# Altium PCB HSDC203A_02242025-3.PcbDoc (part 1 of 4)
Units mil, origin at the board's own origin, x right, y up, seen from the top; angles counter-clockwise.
Board outline 5612.98 x 3012.39 mil, 6 copper layers (Top Layer, GND1, Signal1, Power, GND2, Bottom Layer), stack 60.4 mil thick; 301 components, 211 nets, 1107 pads, 249 vias.
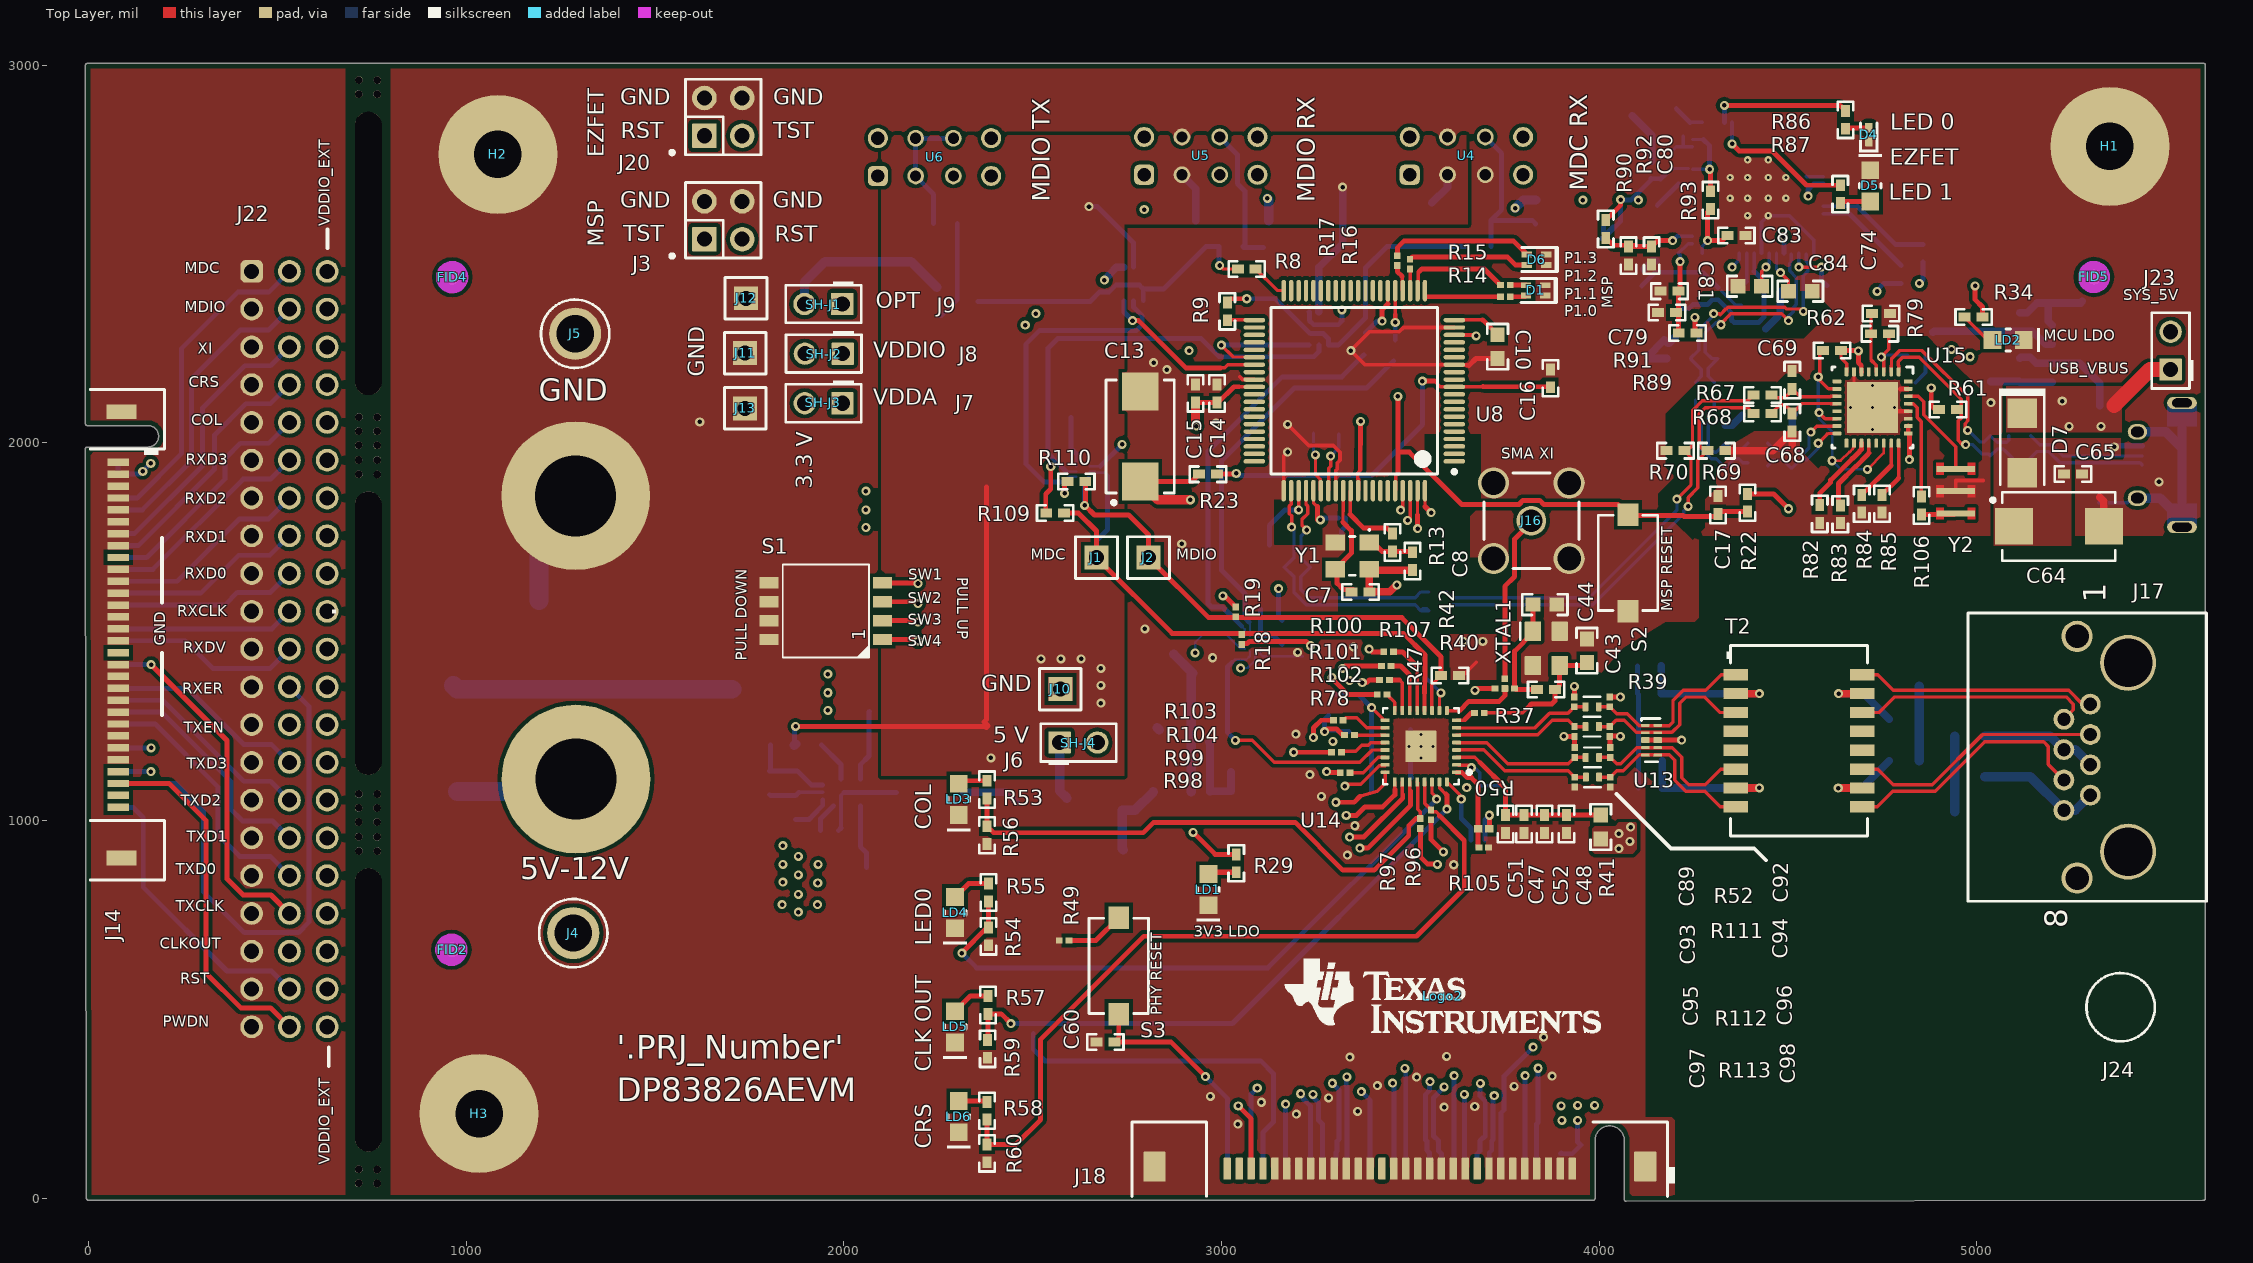
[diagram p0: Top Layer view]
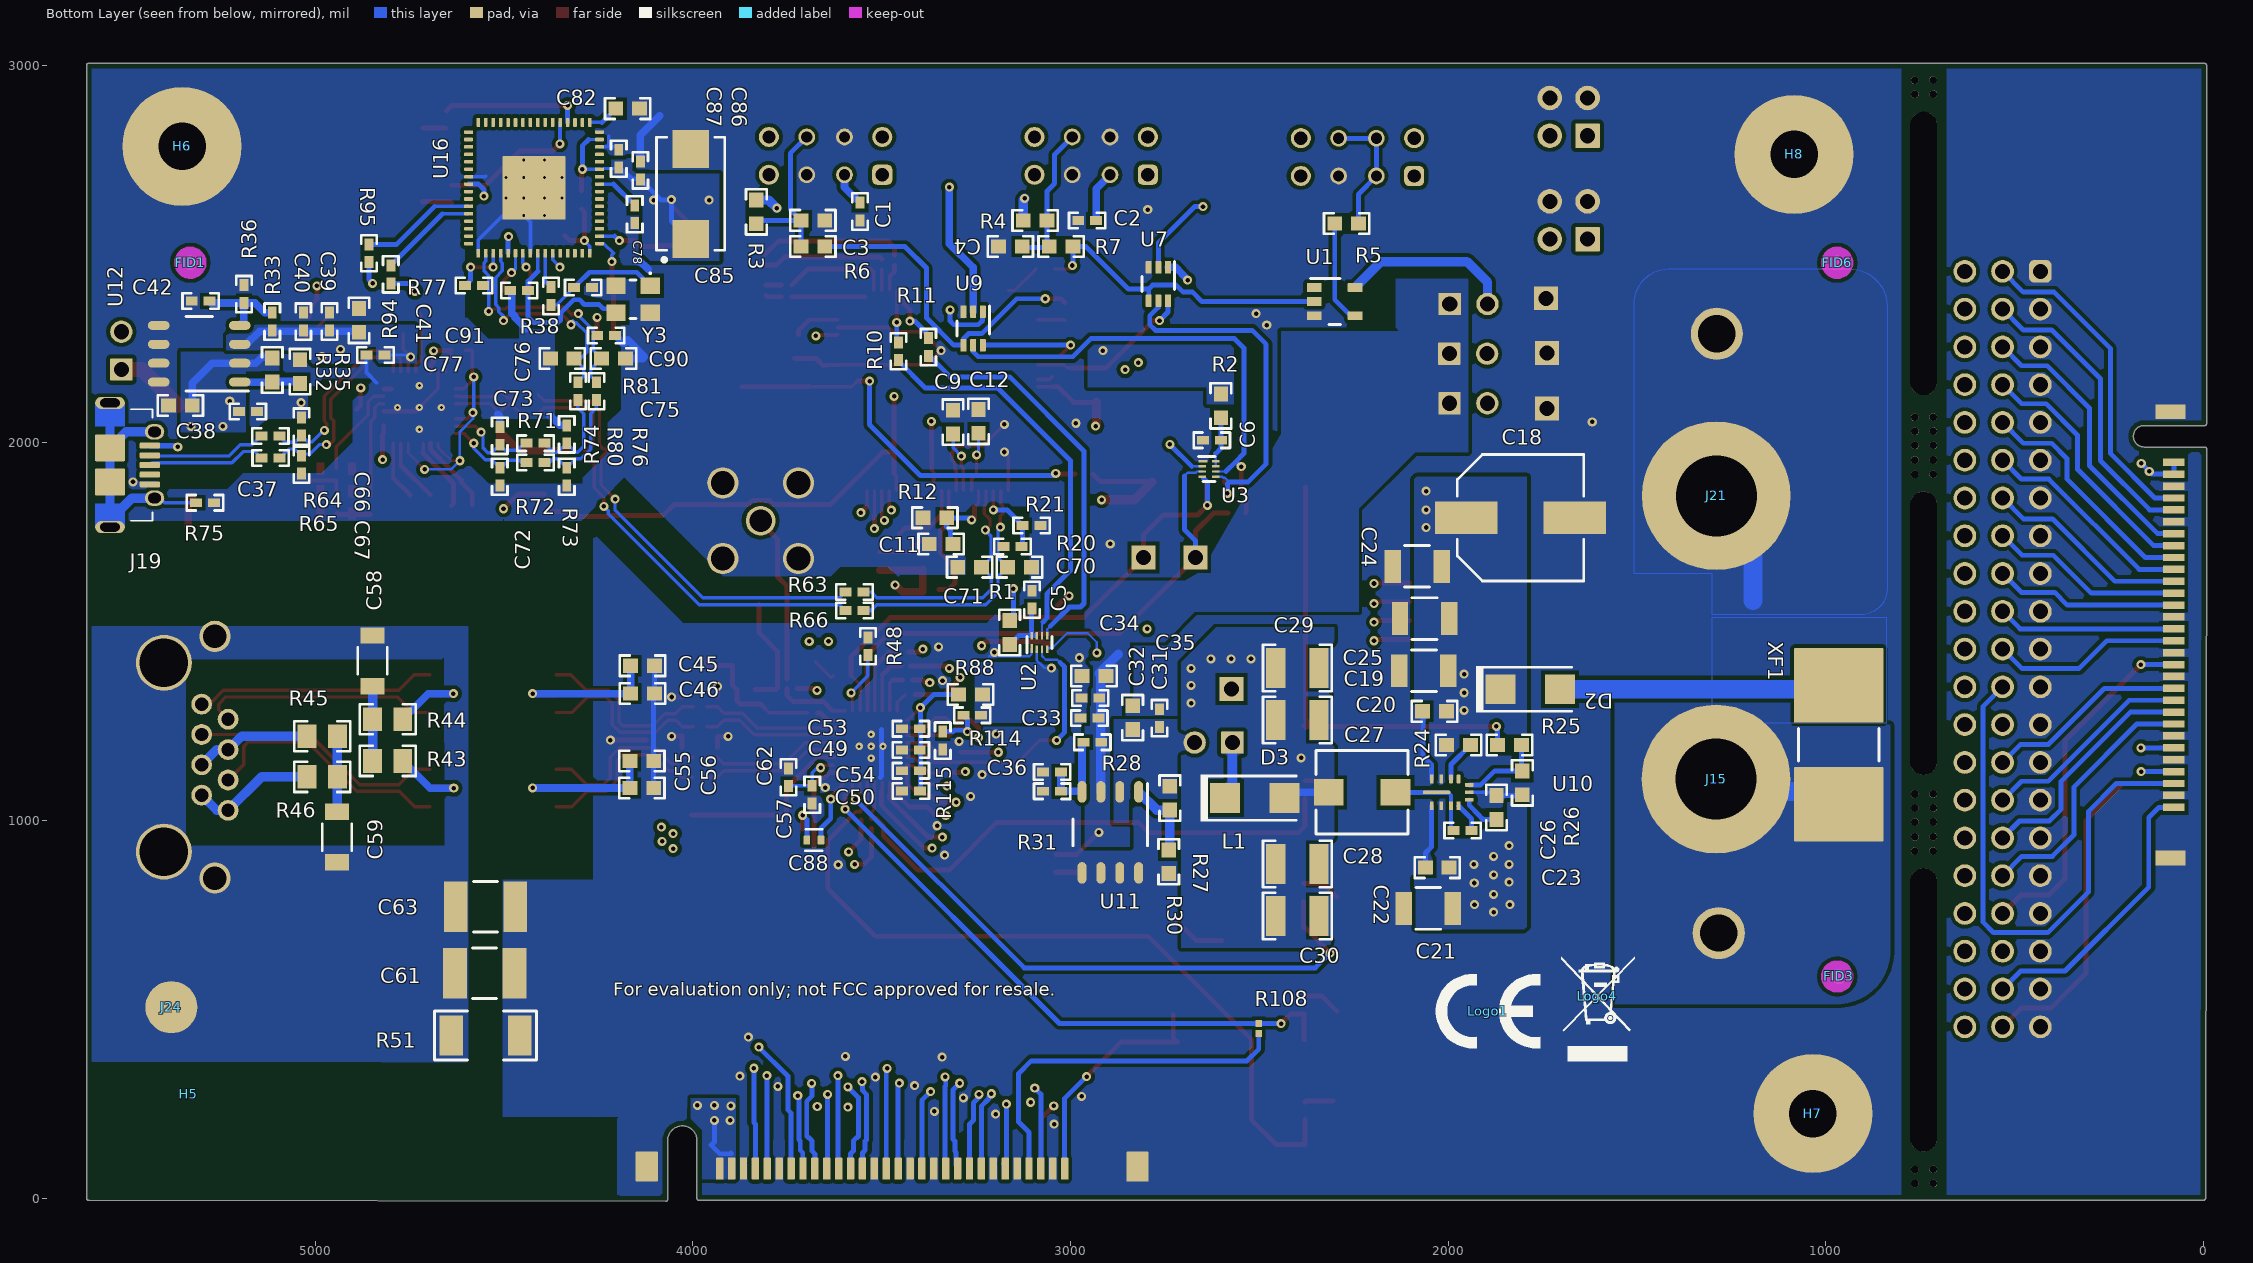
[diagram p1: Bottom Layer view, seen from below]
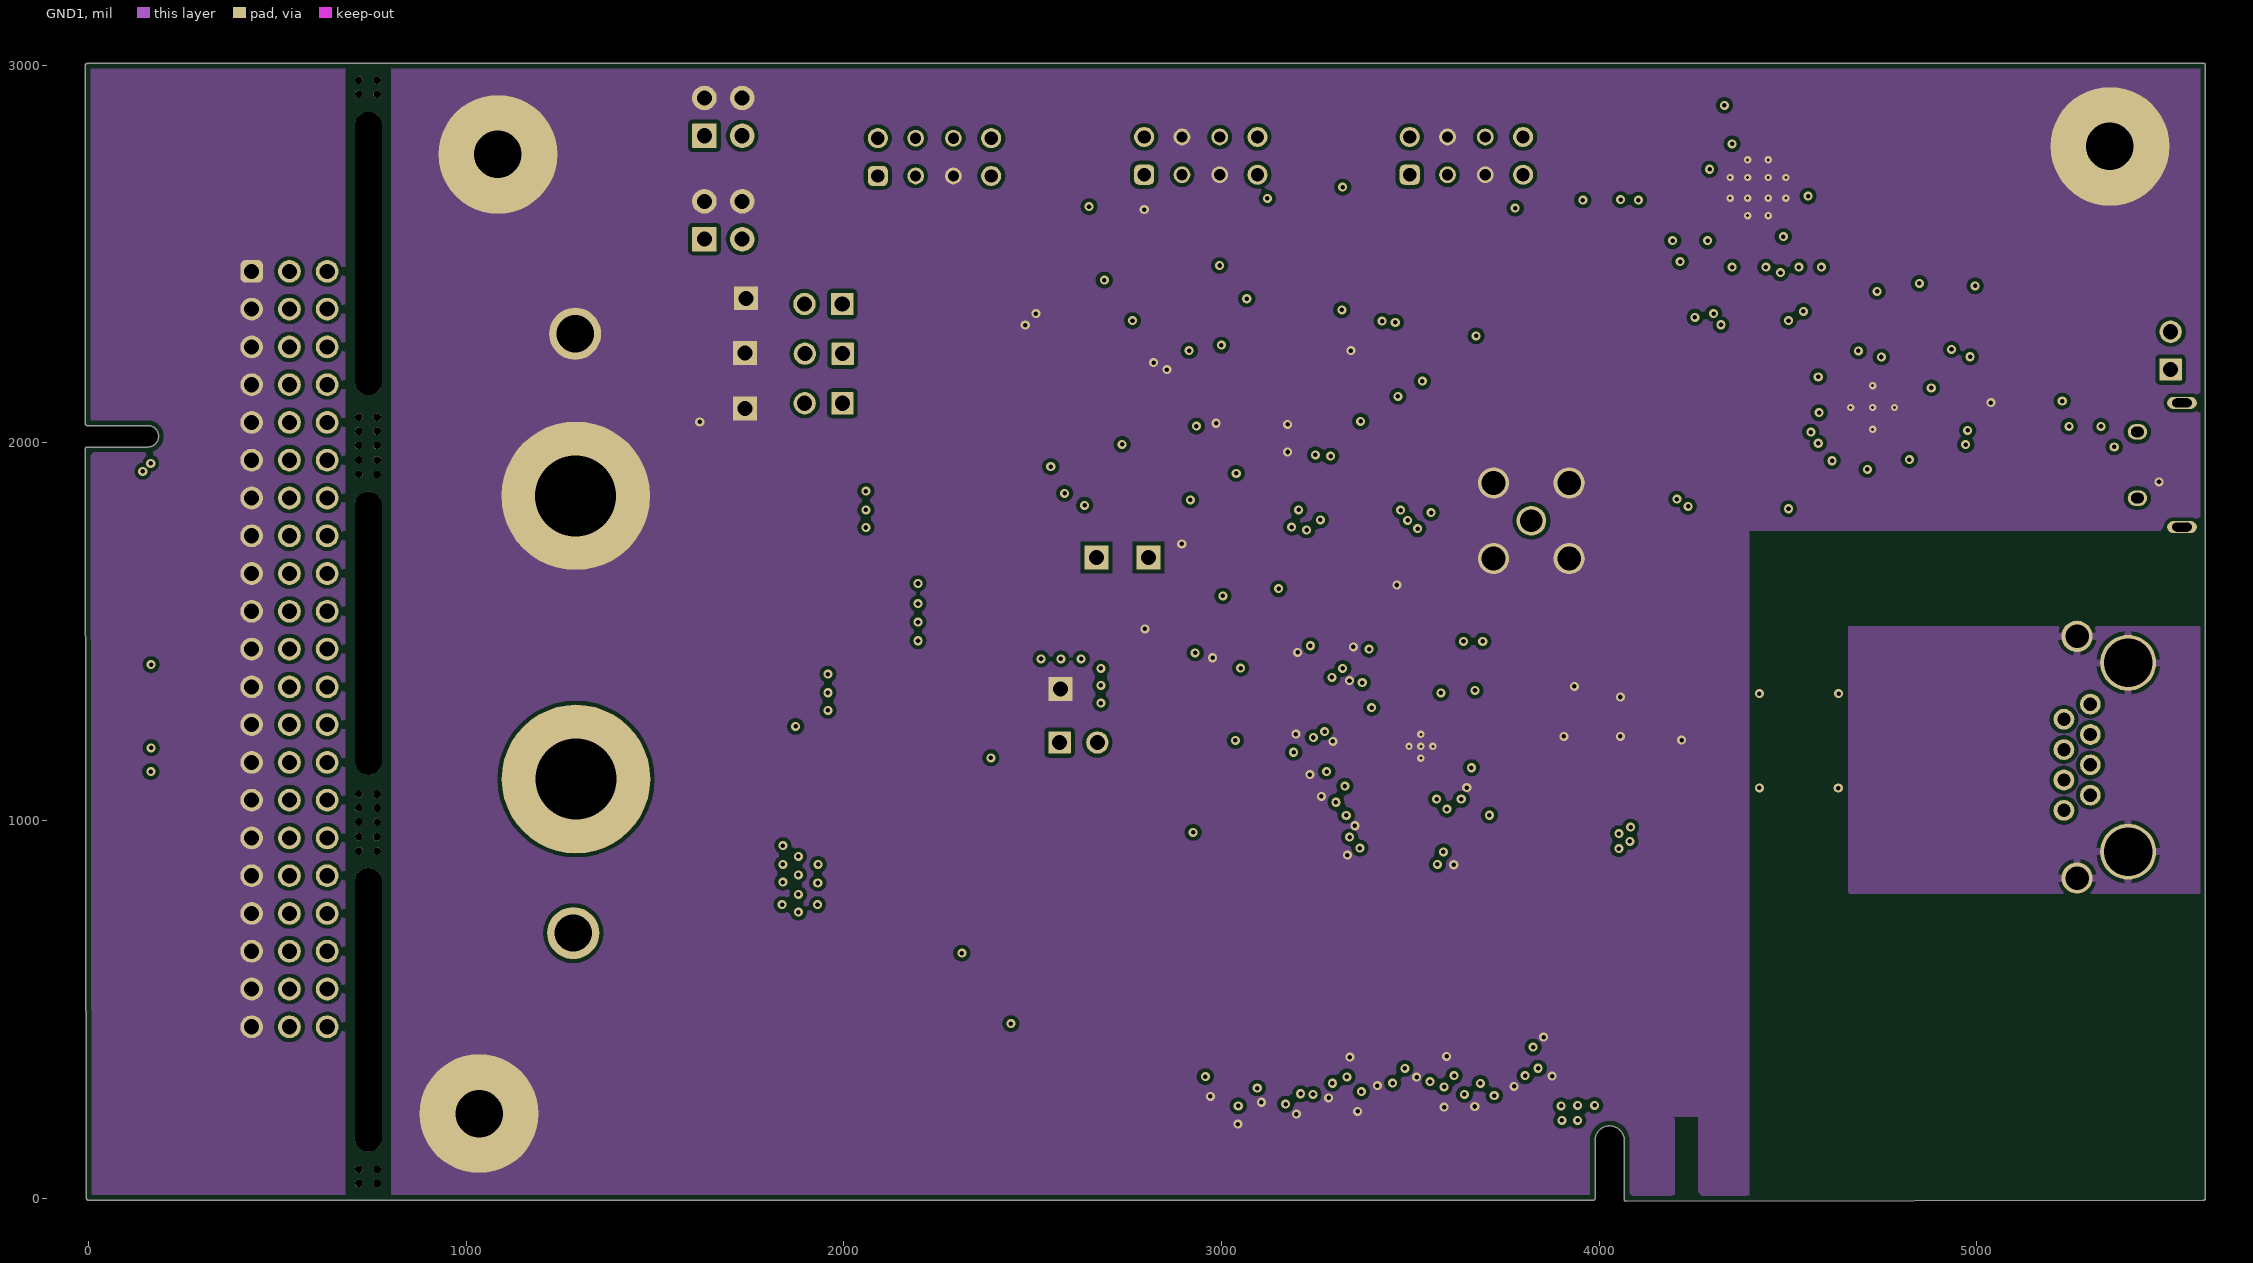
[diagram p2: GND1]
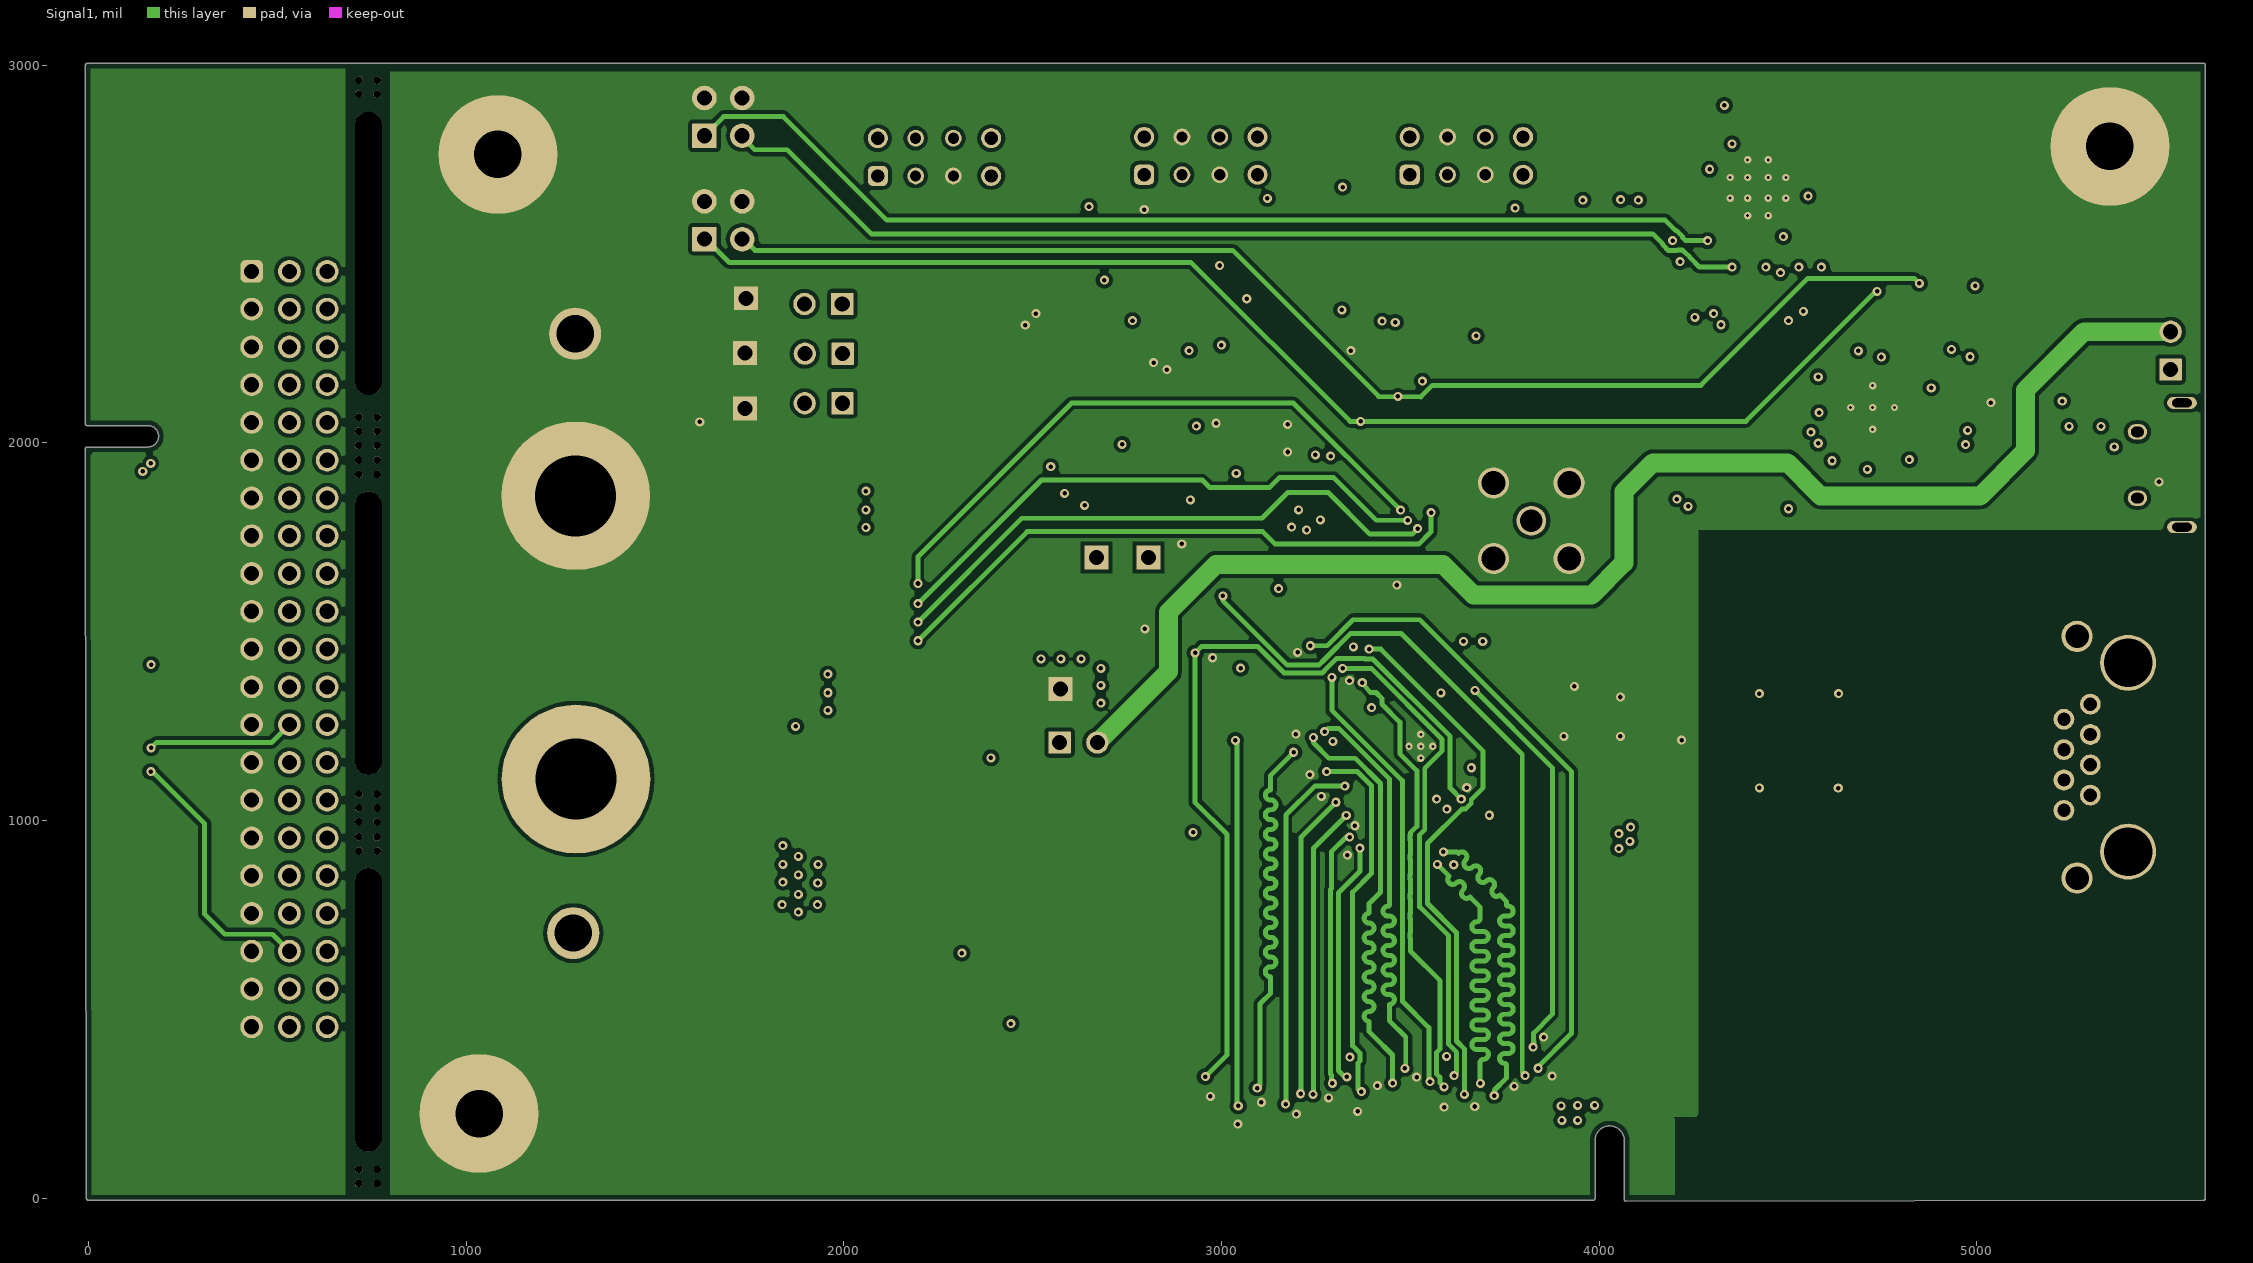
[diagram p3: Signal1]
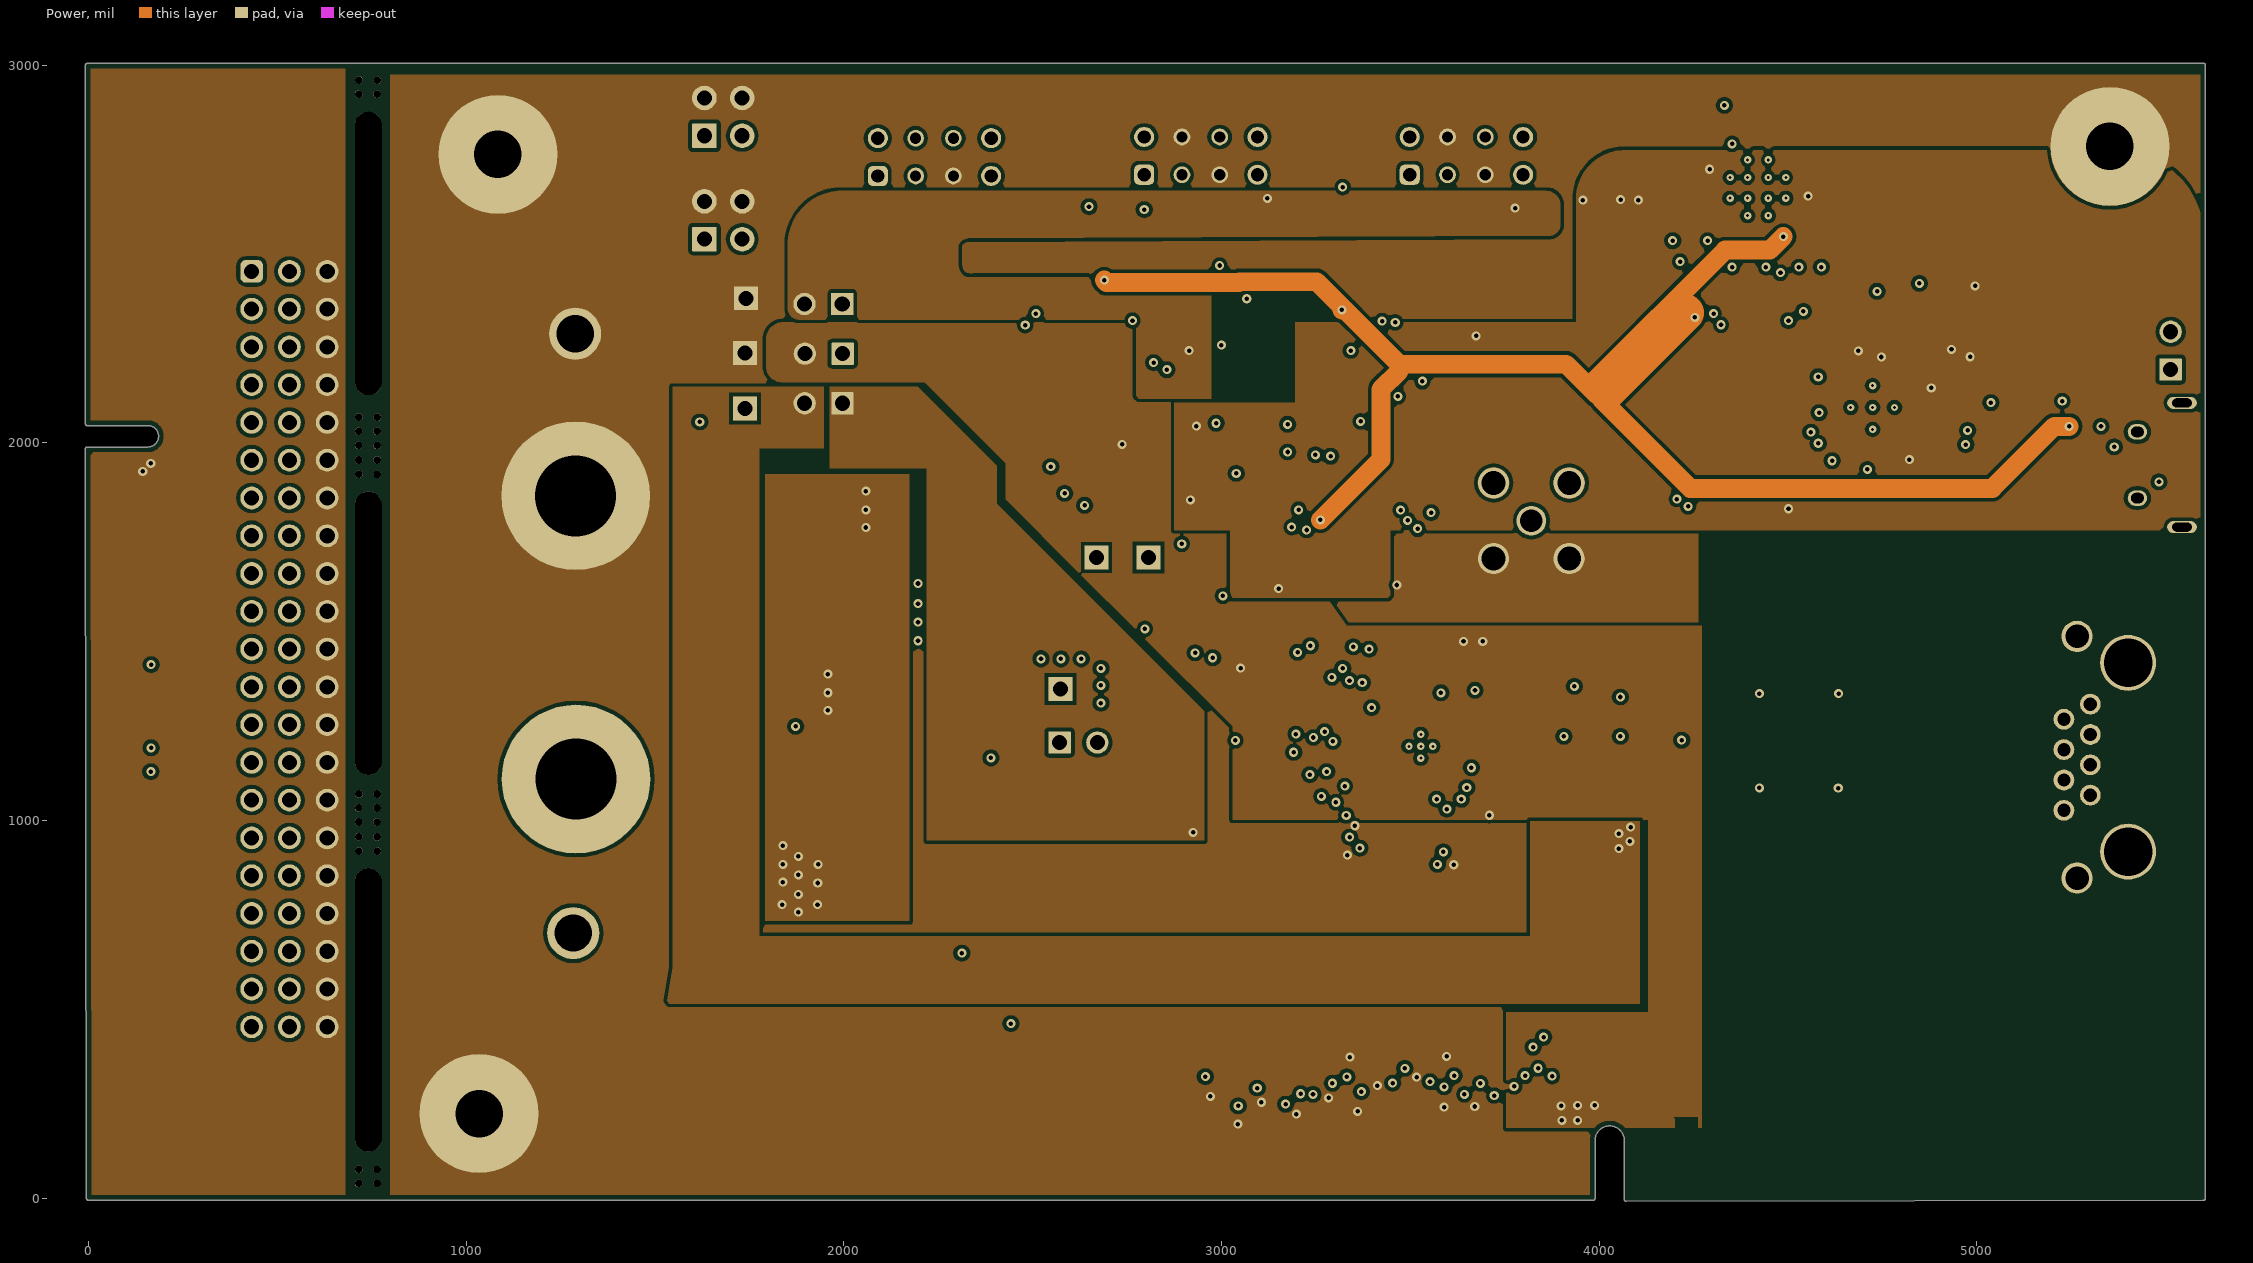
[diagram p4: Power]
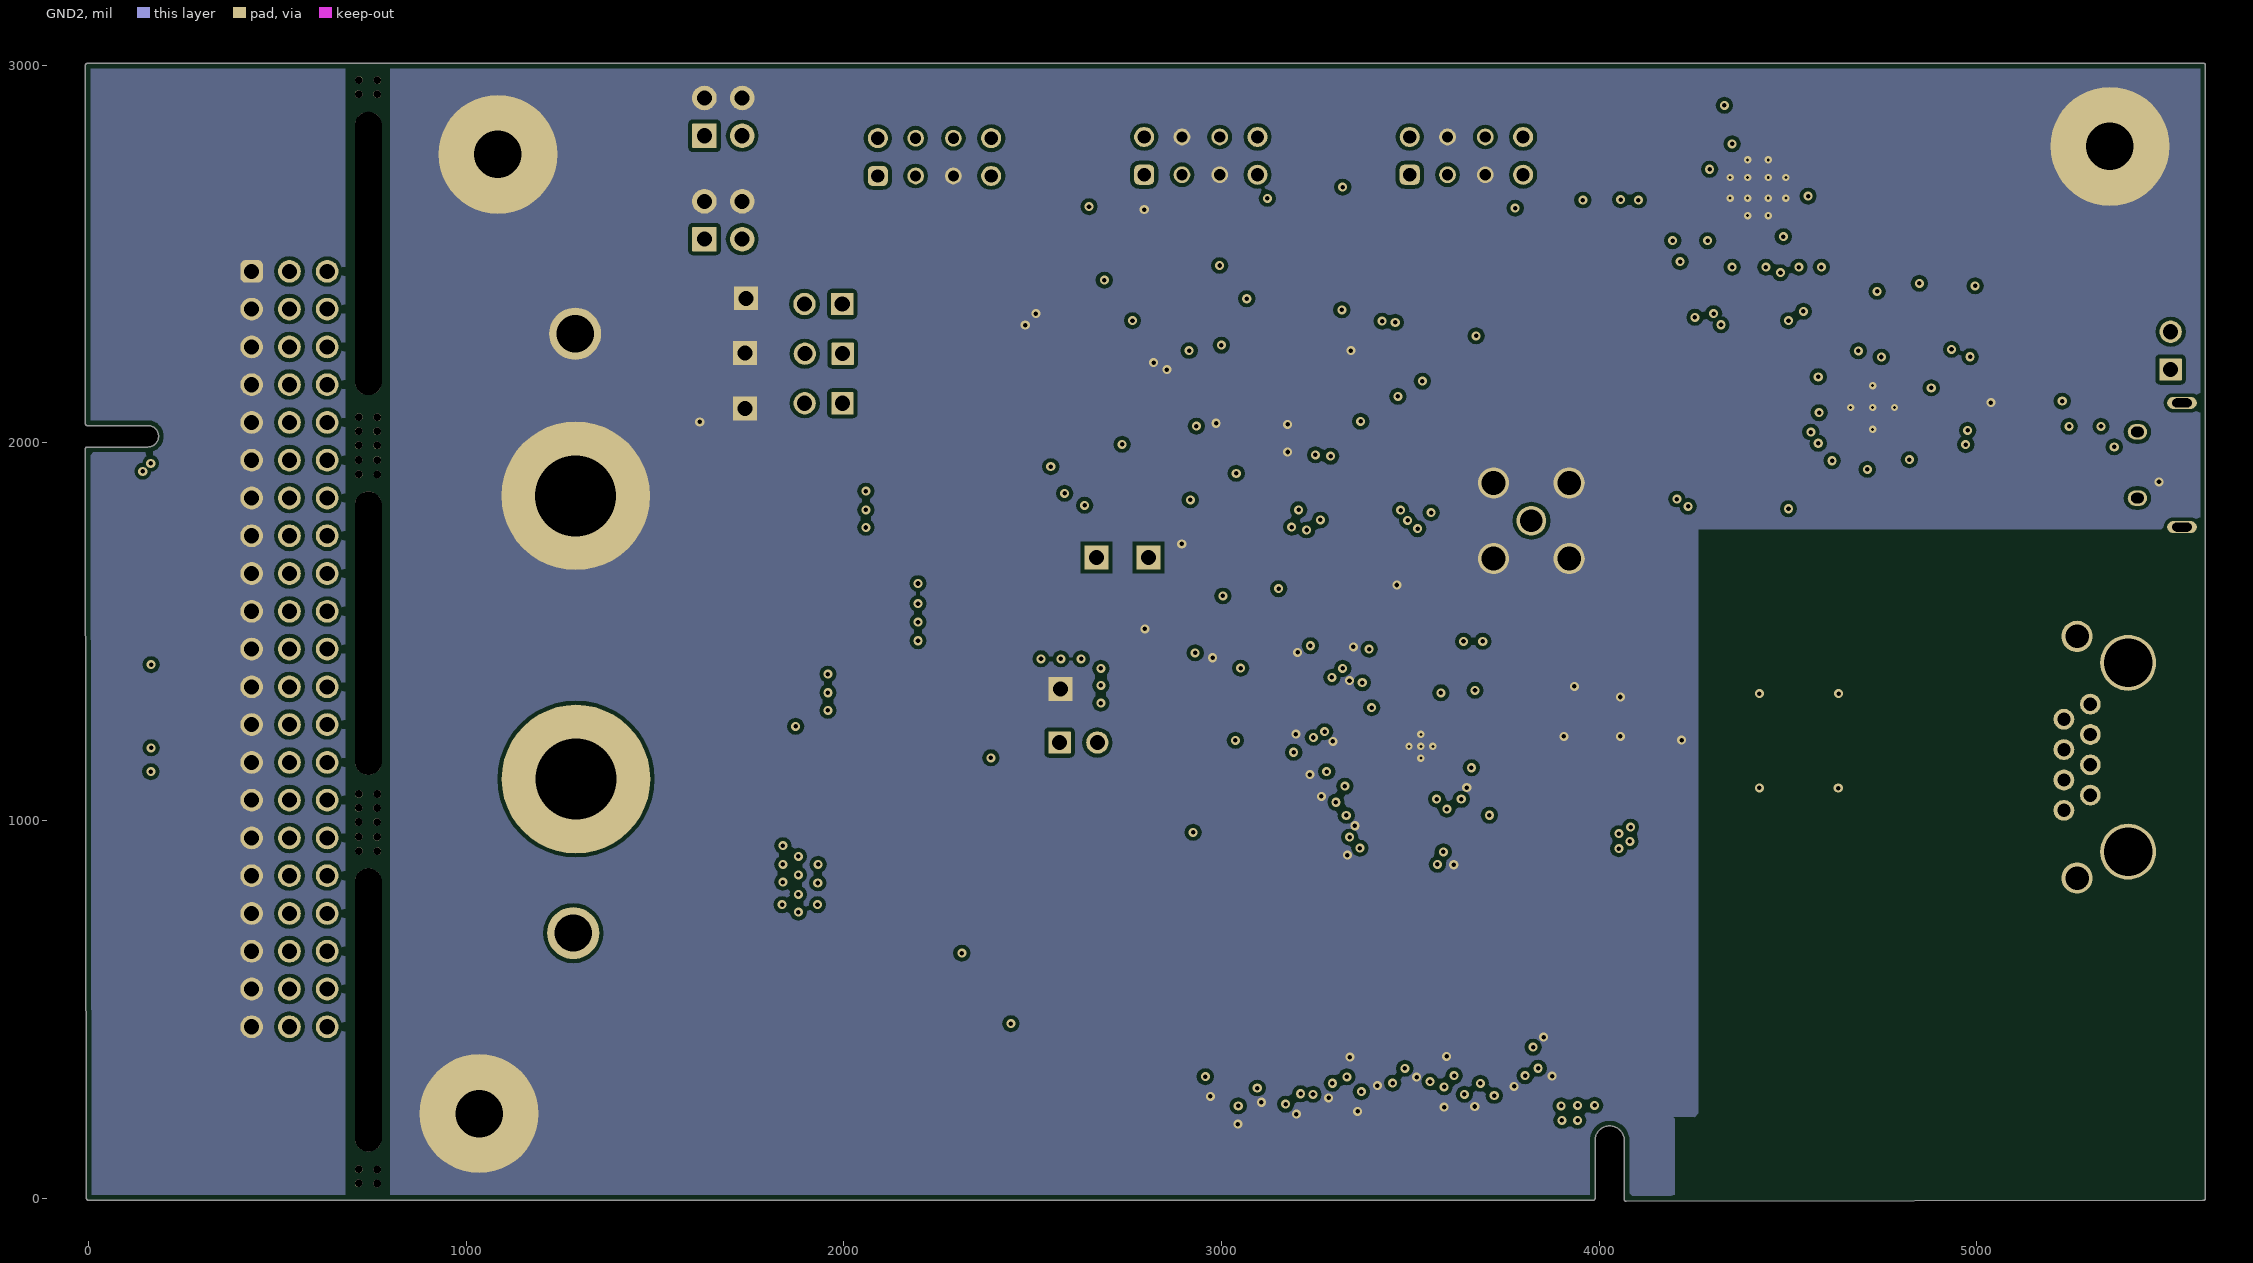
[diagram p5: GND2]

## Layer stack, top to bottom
Top Solder: solder mask 0.7, Solder Resist, Dk 3.5
Top Layer: signal copper 1.4
Dielectric 1: dielectric 7, FR-4 High TG, Dk 4.2
GND1: signal copper 1.4
Dielectric1: core 14, FR-4 High TG, Dk 4.2
Signal1: signal copper 1.4
Dielectric 2: dielectric 10, FR-4 High TG, Dk 4.2
Power: signal copper 1.4
Dielectric 4: core 14, FR-4 High TG, Dk 4.2
GND2: signal copper 1.4
Dielectric 3: dielectric 7, FR-4 High TG, Dk 4.2
Bottom Layer: signal copper 1.4
Bottom Solder: solder mask 0.4, Solder Resist, Dk 3.5

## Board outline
-5.01,-0.01 -7.97,1984.24 cw(c-2.95,1984.25) -2.95,1989.27 157.48,1989.27 ccw(c157.48,2017.72) 185.93,2017.72 ccw(c157.48,2017.72) 157.48,2046.17 -2.95,2046.17 cw(c-2.95,2051.18) -7.97,2051.18 -7.96,3000 cw(c-2.95,3000) -2.88,3005.01 5600,3005.02 cw(c5600,3000) 5605.02,3000 5605.02,0 cw(c5600,0) 5599.02,-4.92 5598.04,-5.02 4071.27,-7.38 cw(c4071.26,-2.36) 4066.39,-1.18 4066.24,0 4066.24,157.76 ccw(c4027.56,152.84) 3988.87,157.76 3988.87,0 cw(c3983.86,0) 3983.86,-5.02 0,-5.02 cw(c0,0)

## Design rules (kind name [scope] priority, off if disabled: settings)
AcuteAngle [All] p1: minimum=4.50000000000000E+0001 checktracksonly=FALSE
AssemblyTestPointUsage [All] p1: valid=2
BoardOutlineClearance BoardOutlineClearance_MountingHoles [OnCopper and InComponentClass('Mounting Holes')] p1: gap=39.37 ignorepadtopadclearanceinfootprint=FALSE
BoardOutlineClearance BoardOutlineClearance_Poly [OnCopper and IsPoly] p2: gap=14 ignorepadtopadclearanceinfootprint=FALSE
BoardOutlineClearance [OnCopper and Not InComponentClass('Logo') and not InComponentClass('FiducialMark') and not InRegion(1000,500,4000,800) and not InPoly] p3: gap=14 ignorepadtopadclearanceinfootprint=FALSE
Clearance Clearance_Keepouts [((IsTrack Or IsArc) And Not InPoly) And IsFree and IsKeepOut vs ((IsTrack Or IsArc) And Not InPoly) And IsFree and IsKeepOut] p1: gap=0 ignorepadtopadclearanceinfootprint=FALSE
Clearance Clearance_Poly [InPolygon] p2: gap=10 ignorepadtopadclearanceinfootprint=TRUE
Clearance Clearance_FiducialMark [IsKeepOut and InComponentClass('FiducialMark') vs IsPad and InComponentClass('FiducialMark')] p3: gap=0 ignorepadtopadclearanceinfootprint=FALSE
Clearance [All] p4: gap=7.87 ignorepadtopadclearanceinfootprint=TRUE except(7.3: Arc-Arc Arc-Track Arc-SMDPad Arc-Via Track-Track Track-SMDPad Track-Via)
ComponentClearance ComponentClearance_CLK_Res [InComponent('R107')  Or  InComponent('R40')  Or  InComponent('R42')] p1: gap=0 collisioncheckmode=3 verticalgap=0 showdistances=FALSE
ComponentClearance ComponentClearance_MountingHoles_FiducialMarks [InComponentClass('Mounting Holes') vs InComponentClass('FiducialMark')] p2: gap=50 collisioncheckmode=3 verticalgap=10 showdistances=FALSE
ComponentClearance ComponentClearance_Shunt [InComponentClass('Header') vs InComponentClass('Shunt')] p3: gap=0 collisioncheckmode=3 verticalgap=0 showdistances=FALSE
ComponentClearance ComponentClearance_Logo [InComponentClass('Logo')] p4: gap=50 collisioncheckmode=3 verticalgap=10 showdistances=FALSE
ComponentClearance ComponentClearance_ScrewToNut [(HasFootprint('NY PMS 440 0025 PH')) vs (HasFootprint('Keystone_1902E'))] p5: gap=5 collisioncheckmode=3 verticalgap=10 showdistances=FALSE
ComponentClearance ComponentClearance_MountingHoles [InComponentClass('Mounting Holes')] p6: gap=250 collisioncheckmode=3 verticalgap=100000 showdistances=FALSE
ComponentClearance ComponentClearance_SmallPassives [HasFootprint('0201*') or HasFootprint('0402*') or HasFootprint('0508') or HasFootprint('0603*') or HasFootprint('0612') or HasFootprint('0805*') or HasFootprint('0815*') or HasFootprint('0830*') or HasFootprint('1206*') or HasFootprint('1210*') or HasFootprint('1808*') or HasFootprint('1812*') or HasFootprint('1825*') or HasFootprint('2010*') or HasFootprint('2220*') or HasFootprint('2225*') or HasFootprint('2512*') or HasFootprint('2728*') or HasFootprint('3518*') vs HasFootprint('0201*') or HasFootprint('0402*') or HasFootprint('0508') or HasFootprint('0603*') or HasFootprint('0612') or HasFootprint('0805*') or HasFootprint('0815*') or HasFootprint('0830*') or HasFootprint('1206*') or HasFootprint('1210*') or HasFootprint('1808*') or HasFootprint('1812*') or HasFootprint('1825*') or HasFootprint('2010*') or HasFootprint('2220*') or HasFootprint('2225*') or HasFootprint('2512*') or HasFootprint('2728*') or HasFootprint('3518*')] p7: gap=14.96 collisioncheckmode=3 verticalgap=10 showdistances=FALSE
ComponentClearance ComponentClearance_THtoSMT [IsThruComponent vs IsSMTComponent] p8: gap=10 collisioncheckmode=3 verticalgap=30 showdistances=FALSE
ComponentClearance ComponentClearance_THtoTH [IsThruComponent vs IsThruComponent] p9: gap=30 collisioncheckmode=3 verticalgap=30 showdistances=FALSE
ComponentClearance [All] p10: gap=20 collisioncheckmode=3 verticalgap=10 showdistances=FALSE
DiffPairsRouting [All] p1: maxlimit=9 minlimit=9 mostfreqgap=9 toplayer_minwidth=8 toplayer_maxwidth=9 toplayer_prefwidth=9 midlayer1_minwidth=9 midlayer1_maxwidth=9 midlayer1_prefwidth=9 midlayer2_minwidth=9 midlayer2_maxwidth=9 midlayer2_prefwidth=9 midlayer3_minwidth=9 midlayer3_maxwidth=9 midlayer3_prefwidth=9 midlayer4_minwidth=9 midlayer4_maxwidth=9 midlayer4_prefwidth=9 bottomlayer_minwidth=8 bottomlayer_maxwidth=9 bottomlayer_prefwidth=9 maxuncoupledlength=1000
FabricationTestPointUsage TestPointUsage [All] p1: valid=2 allowmultiple=FALSE
FabricationTestpoint Testpoint [All] p1: side=3 testpointundercomponent=TRUE minsize=40 maxsize=100 preferedsize=60 minholesize=0 maxholesize=40 preferedholesize=32 testpointgrid=1 allowsidetop=TRUE allowsidebottom=TRUE usegrid=TRUE gridtolerance=0.01
FanoutControl Fanout_LCC [IsLCC] p1: bgadir=Out bgaviamode=Centered fanoutstyle=Auto fanoutdirection=Alternating viagrid=1 // Fanout_LCC (Default Rule)
FanoutControl Fanout_BGA [IsBGA] p2: bgadir=Out bgaviamode=Centered fanoutstyle=Auto fanoutdirection=Alternating viagrid=1 // Fanout_BGA (Default Rule)
FanoutControl Fanout_Default [All] p4: bgadir=Out bgaviamode=Centered fanoutstyle=Auto fanoutdirection=Alternating viagrid=1 // Fanout_Default (Default Rule)
FanoutControl Fanout_Small [(CompPinCount < 5)] p5: bgadir=Out bgaviamode=Centered fanoutstyle=Auto fanoutdirection=OutThenIn viagrid=1 // Fanout_Small (Default Rule)
Height [All] p1: minheight=0 maxheight=1005 prefheight=500
HoleSize HoleSize_1 [IsPad And HasSlotHole] p1: absolutevalues=TRUE maxlimit=751 minlimit=1 maxpercent=80.000 minpercent=20.000
HoleSize [All] p2: absolutevalues=TRUE maxlimit=300 minlimit=6 maxpercent=80.000 minpercent=20.000
MinimumAnnularRing MinimumAnnularRing_J19 [InComponent('J19')] p1: minimumring=3.9
MinimumAnnularRing MinimumAnnularRing_ThermalPadVias [IsVia and InAnyComponent] p2: minimumring=5.91
MinimumAnnularRing [All] p3: minimumring=5
MinimumSolderMaskSliver MinimumSolderMaskSliver_U2U3 [InPadClass('All Pads')] p1: minsoldermaskwidth=3
MinimumSolderMaskSliver MinimumSolderMaskSliver_Logo [InComponentClass('Logo') vs InComponentClass('Logo')] p2: minsoldermaskwidth=0.7
MinimumSolderMaskSliver [All] p3: minsoldermaskwidth=3.94
PlaneConnect [All] p1: planeconnectstyle=Direct reliefexpansion=10 reliefentries=4 reliefconductorwidth=10 reliefairgap=10
PolygonConnect PolygonConnect_EGND [InNet('EARTH_GND') vs OnLayer('GND1')] p1: connectstyle=Relief reliefconductorwidth=20 reliefentries=4 polygonreliefangle="90 Angle" airgapwidth=10
PolygonConnect [All] p2: connectstyle=Direct reliefconductorwidth=20 reliefentries=4 polygonreliefangle="90 Angle" airgapwidth=10
RoutingVias ThermalPadVias [IsVia and InAnyComponent] p1: holewidth=7.87 width=19.68 viastyle="Through Hole" minholewidth=7.87 minwidth=19.68 maxholewidth=12.99 maxwidth=23.62
RoutingVias [All] p2: holewidth=12 width=24 viastyle="Through Hole" minholewidth=6 minwidth=12 maxholewidth=40 maxwidth=65
ShortCircuit ShortCircuit_Y2 [InComponent('Y2')] p1: allowed=TRUE
ShortCircuit [All] p2: allowed=FALSE
SilkToBoardRegionClearance [Not ((IsComment or IsDesignator) And (Hide <> 'False')) and not InRegion(1000,500,4000,800)] p1:
SilkToSilkClearance SilkToSilkClearance_Pb-FreeLogo [(HasFootprint('Pb-Free_Overlay_Medium') OR HasFootprint('Pb-Free_Overlay_Small')) vs (HasFootprint('Pb-Free_Overlay_Medium') OR HasFootprint('Pb-Free_Overlay_Small'))] p1: silktosilkclearance=0
SilkToSilkClearance [All] p2: silktosilkclearance=3.94
SilkToSolderMaskClearance [InComponent('D2')  OR InComponent('D3')] p1: minsilkscreentomaskgap=3.9 clearancetoexposedcopper=TRUE
SilkToSolderMaskClearance SilkToComponentPadClearance [(IsPad or IsFill or IsRegion) and InAnycomponent] p2: minsilkscreentomaskgap=4 clearancetoexposedcopper=TRUE
SilkToSolderMaskClearance "Silk to Solder Mask Opening" [All] p3: minsilkscreentomaskgap=3.94 clearancetoexposedcopper=FALSE
SolderMaskExpansion [All] p1: expansion=1.97 istentingtop=FALSE
SupplyNets "Schematic Supply Nets_12" [InNet('3V3_LDO')] p1: voltage=0.000
SupplyNets "Schematic Supply Nets_11" [InNet('GND_EXT')] p2: voltage=0.000
SupplyNets "Schematic Supply Nets_10" [InNet('VDDIO')] p3: voltage=0.000
SupplyNets "Schematic Supply Nets_9" [InNet('5V-12V')] p4: voltage=0.000
SupplyNets "Schematic Supply Nets_8" [InNet('VDDIO_EXT')] p5: voltage=0.000
SupplyNets "Schematic Supply Nets_7" [InNet('USB_VBUS')] p6: voltage=0.000
SupplyNets "Schematic Supply Nets_6" [InNet('EARTH_GND')] p7: voltage=0.000
SupplyNets "Schematic Supply Nets_5" [InNet('5V')] p8: voltage=0.000
SupplyNets "Schematic Supply Nets_4" [InNet('VDDA3P3')] p9: voltage=0.000
SupplyNets "Schematic Supply Nets_2" [InNet('GND')] p10: voltage=0.000
SupplyNets "Schematic Supply Nets_1" [InNet('3V3_OPT')] p11: voltage=0.000
SupplyNets "Schematic Supply Nets" [InNet('MCU_VCC')] p12: voltage=0.000
Width [All] p1: maxlimit=100 minlimit=6 preferedwidth=13 midlayer1_minwidth=7 midlayer2_minwidth=7 midlayer3_minwidth=7 midlayer4_minwidth=7 minimp=50.000000 maximp=50.000000 favimp=50.000000 checkconnectedcopper=TRUE
13 further rules are at their usual default settings.

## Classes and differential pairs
component class SHUNT: SH-J1 SH-J2 SH-J3 SH-J4
component class HSDC203A_Power: C18 C19 C20 C21 C22 C23 C24 C25 C26 C27 C28 C29 C30 C31 C32 C33 C34 C35 C36 C37 C38 C39 C40 C41 C42 D2 D3 J4 J5 J6 J7 J8 J9 J10 J11 J12 J13 J15 J21 J23 L1 LD1 LD2 R24 R25 R26 R27 R28 R29 R30 R31 R32 R33 R34 R35 R36 U10 U11 U12 XF1
component class HSDC203A_Main: C43 C44 C45 C46 C47 C48 C49 C50 C51 C52 C53 C54 C55 C56 C57 C58 C59 C60 C61 C62 C63 C88 C89 C92 C93 C94 C95 C96 C97 C98 J16 J17 J18 J24 LD3 LD4 LD5 LD6 R18 R19 R37 R39 R40 R41 R42 R43 R44 R45 R46 R47 R48 R49 R50 R51 R52 R53 R54 R55 R56 R57 R58 R59 R60 R78 R88 R96 R97 R98 R99 R100 R101 R102 R103 R104 R105 R107 R108 R111 R112 R113 R114 R115 S3 T2 U13 U14 XTAL1
component class HSDC203A_Hub_EZFET: C64 C65 C66 C67 C68 C69 C70 C71 C72 C73 C74 C75 C76 C77 C78 C79 C80 C81 C82 C83 C84 C85 C86 C87 C90 C91 D4 D5 D7 J19 J20 R38 R61 R62 R63 R64 R65 R66 R67 R68 R69 R70 R71 R72 R73 R74 R75 R76 R77 R79 R80 R81 R82 R83 R84 R85 R86 R87 R89 R90 R91 R92 R93 R94 R95 R106 U15 U16 Y2 Y3
component class HSDC203A_Coms: C1 C2 C3 C4 C5 C6 C7 C8 C9 C10 C11 C12 C13 C14 C15 C16 C17 D1 D6 J1 J2 J3 R1 R2 R3 R4 R5 R6 R7 R8 R9 R10 R11 R12 R13 R14 R15 R16 R17 R20 R21 R22 R23 R109 R110 S1 S2 U1 U2 U3 U4 U5 U6 U7 U8 U9 Y1
component class HSDC203A_Breakout: J14 J22
component class Header: J3 J6 J7 J8 J9 J20 J22 J23
component class "Mounting Holes": H1 H2 H3
component class Logo: Logo2
component class HSDC203A_Hardware: FID1 FID2 FID3 FID4 FID5 FID6 H1 H2 H3 H5 H6 H7 H8 Logo1 Logo2 Logo3 Logo4 SH-J1 SH-J2 SH-J3 SH-J4 ZZ1 ZZ2 ZZ3 ZZ4
component class FiducialMark: FID1 FID2 FID3 FID4 FID5 FID6
component class AssemblyNote: ZZ1 ZZ2 ZZ3 ZZ4
differential pair USB: +USB_P -USB_N
differential pair TD: +TD_P -TD_N
differential pair TD_CH2: +TD_CH2_P -TD_CH2_N
differential pair TD_CH1: +TD_CH1_P -TD_CH1_N
differential pair TARGET_D: +TARGET_D_P -TARGET_D_N
differential pair RD: +RD_P -RD_N
differential pair HUB_D2: +HUB_D2_P -HUB_D2_N
differential pair HUB_D1: +HUB_D1_P -HUB_D1_N
differential pair EZFET_PUD: +EZFET_PUD_P -EZFET_PUD_N
differential pair D2: +D2_P -D2_N
differential pair D1: +D1_P -D1_N
differential pair D0: +D0_P -D0_N

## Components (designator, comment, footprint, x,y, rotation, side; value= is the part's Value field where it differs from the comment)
C1 "GCM155R71H104KE02D" 0402 3557.19,2612.73 r270 bottom value=0.1uF
C2 "GCM155R71H104KE02D" 0402 2955.77,2588.81 r0 bottom value=0.1uF
C3 "CGA3E2C0G1H220J080AA" 0603 3682.06,2589.41 r180 bottom value=22pF
C4 "CGA3E2C0G1H220J080AA" 0603 3159.06,2519.98 r0 bottom value=22pF
C5 "GCM155R71H104KE02D" 0402 3101.97,1585.05 r90 bottom value=0.1uF
C6 "GCM155R71H104KE02D" 0402 2625.59,2007.12 r0 bottom value=0.1uF
C7 "CL05C360JB5NNNC" 0402 3367.88,1605.55 r0 top value=36pF
C8 "CL05C360JB5NNNC" 0402 3505.51,1687.18 r270 top value=36pF
C9 "C0603C224Z4VACTU" 0603 3310.86,2055.12 r90 bottom value=0.22uF
C10 "GCM188R71C474KA55D" 0603 3731.07,2255.15 r270 top value=0.47uF
C11 "C1608X5R1V475K080AC" 0603 3342.4,1732.28 r180 bottom value=4.7uF
C12 "C0603C224Z4VACTU" 0603 3243.41,2057.09 r90 bottom value=0.22uF
C13 "TPSD106K035R0125" 7343-31 2784.75,2017.07 r90 top value=10uF
C14 "C0402C104K8RACTU" 0402 2987.94,2131.24 r90 top value=0.1uF
C15 "C0402C104K8RACTU" 0402 2931.18,2131.24 r90 top value=0.1uF
C16 "C0402C104K8RACTU" 0402 3871.17,2171.29 r90 top value=0.1uF
C17 "C1005NP01H102J050BA" 0402 4314.08,1835.86 r270 top value=1000pF
C18 "EMVE500ADA101MHA0G" CAPSMT_62_HA0 1808.42,1802 r180 bottom value=100uF
C19 "CGA6P3X7R1H475K250AB" 1210_280 2064.36,1396.9 r0 bottom value=4.7uF
C20 "CGA3E3X7R1H224K080AB" 0603 2036.33,1289.57 r0 bottom value=0.22uF
C21 "CGA6P3X7R1H475K250AB" 1210_280 2052.76,767.72 r0 bottom value=4.7uF
C22 "CGA3E3X7R1H224K080AB" 0603 2028.93,875.7 r0 bottom value=0.22uF
C23 "GCM155R71H104KE02D" 0402 1961.93,973.67 r0 bottom value=0.1uF
C24 "CGA6P1X7R1C226M250AC" 1210_280 2082.28,1673.23 r0 bottom value=22uF
C25 "CGA6P1X7R1E106M250AC" 1210_280 2062.52,1535.08 r0 bottom value=10uF
C26 "CGA3E1X7R1V105K080AC" 0603 1872.19,1034.7 r90 bottom value=1uF
C27 "TMK325B7226KMHP" 1210_270 2399.22,1266.35 r180 bottom value=22uF
C28 "TMK325B7226KMHP" 1210_270 2399.22,885.48 r180 bottom value=22uF
C29 "TMK325B7226KMHP" 1210_270 2399.22,1404.14 r180 bottom value=22uF
C30 "TMK325B7226KMHP" 1210_270 2399.22,747.69 r180 bottom value=22uF
C31 "GRM155R6YA105ME11D" 0402 2764.31,1271.41 r90 bottom value=1uF
C32 "GRM188R6YA106MA73D" 0603 2835.26,1272.69 r90 bottom value=10uF
C33 "GRM155C81C225KE11D" 0402 2949.84,1271.39 r0 bottom value=2.2uF
C34 "GRM155C81C225KE11D" 0402 2947.56,1324.8 r0 bottom value=2.2uF
C35 "GRM188R6YA106MA73D" 0603 2937.72,1383.07 r0 bottom value=10uF
C36 "GCM155R71H471KA37D" 0402 3048.75,1128.9 r0 bottom value=470pF
C37 "GRM155R6YA105ME11D" 0402 5177.77,2083.2 r180 bottom value=1uF
C38 "GRM188R6YA106MA73D" 0603 5356.65,2099.18 r0 bottom value=10uF
C39 "GRM155C81C225KE11D" 0402 4962.2,2321.44 r90 bottom value=2.2uF
C40 "GRM155C81C225KE11D" 0402 5031.1,2321.33 r90 bottom value=2.2uF
C41 "GRM188R6YA106MA73D" 0603 4883.46,2324.8 r90 bottom value=10uF
C42 "GCM155R71H471KA37D" 0402 5302.95,2375.54 r0 bottom value=470pF
C43 "CGA3E2C0G1H220J080AA" 0603 3967.27,1450 r90 top value=22pF
C44 "CGA3E2C0G1H220J080AA" 0603 3855.98,1571.94 r0 top value=22pF
C45 "C0603C104K8RACTU" 0603 4133.03,1410.13 r180 bottom value=0.1uF
C46 "GRM1885C1H202JA01D" 0603 4133.03,1336.54 r180 bottom value=2000pF
C47 "C0402C104K8RACTU" 0402 3801.17,991.36 r270 top value=0.1uF
C48 "CL05A106MQ5NUNC" 0402 3912.99,991.36 r270 top value=10uF
C49 "C0402C104K8RACTU" 0402 3422.72,1187.17 r0 bottom value=0.1uF
C50 "CL05A106MQ5NUNC" 0402 3422.49,1078.66 r0 bottom value=10uF
C51 "885012205031" 0402 3751.85,991.36 r270 top value=0.01uF
C52 "GRM155R70J105KA12D" 0402 3855.25,991.36 r270 top value=1uF
C53 "885012205031" 0402 3422.72,1243.5 r0 bottom value=0.01uF
C54 "GRM155R70J105KA12D" 0402 3422.45,1132.14 r0 bottom value=1uF
C55 "C0603C104K8RACTU" 0603 4134.95,1158.23 r180 bottom value=0.1uF
C56 "GRM1885C1H202JA01D" 0603 4134.95,1086.54 r180 bottom value=2000pF
C57 "C0402C104K8RACTU" 0402 3683.86,1068.75 r270 bottom value=0.1uF
C58 "C1206C102KGRACAUTO" 1206_180 4847.75,1423.31 r90 bottom value=1000pF
C59 "C1206C102KGRACAUTO" 1206_180 4941.64,956.41 r270 bottom value=1000pF
C60 "885012205031" 0402 2692.67,413.77 r180 top value=0.01uF
C61 "1812GC472KAT1A" 1812_254 4551.12,595.76 r0 bottom value=4700pF
C62 "C0402C104K8RACTU" 0402 3746.85,1114.98 r90 bottom value=0.1uF
C63 "1812GC472KAT1A" 1812_254 4548.75,772.16 r0 bottom value=4700pF
C64 "293D475X9035D2TE3" 7343-31 5216.97,1779.04 r0 top value=4.7uF
C65 "C0402C104K8RACTU" 0402 5254.21,1917.58 r180 top value=0.1uF
C66 "C1005NP01H220J050BA" 0402 5035.72,2043.31 r90 bottom value=22pF
C67 "C1005NP01H220J050BA" 0402 5035.72,1942.58 r270 bottom value=22pF
C68 "C1005NP01H220J050BA" 0402 4510.93,2054.36 r270 top value=22pF
C69 "C1005NP01H220J050BA" 0402 4510.93,2166.57 r90 top value=22pF
C70 "CGA3E2NP01H100D080AA" 0603 3134.95,1671.14 r0 bottom value=10pF
C71 "CGA3E2NP01H100D080AA" 0603 3266.84,1671.14 r180 bottom value=10pF
C72 "C1005NP01H220J050BA" 0402 4510.93,1910.66 r270 bottom value=22pF
C73 "C1005NP01H220J050BA" 0402 4510.93,2018.93 r90 bottom value=22pF
C74 "CL05B104KO5NNNC" 0402 4745.97,2342.61 r0 top value=0.1uF
C75 "CGA3E2NP01H100D080AA" 0603 4210.05,2223.66 r180 bottom value=10pF
C76 "CGA3E2NP01H100D080AA" 0603 4345.58,2223.66 r0 bottom value=10pF
C77 "CL05B104KO5NNNC" 0402 4840.16,2232.88 r0 bottom value=0.1uF
C78 "CL05B104KO5NNNC" 0402 4153.65,2605.55 r270 bottom value=0.1uF
C79 "GCM1555C1H330JA16D" 0402 4186.13,2401.81 r180 top value=33pF
C80 "GCM1555C1H330JA16D" 0402 4138.89,2496.07 r270 top value=33pF
C81 "CL10A224KB8NNNC" 0603 4398.51,2414.99 r180 top value=0.22uF
C82 "CGA3E3X7R1H474K080AB" 0603 4172.35,2885.07 r180 bottom value=0.47uF
C83 "C1005NP01H102J050BA" 0402 4363.3,2549.21 r0 top value=1000pF
C84 "CL10A224KB8NNNC" 0603 4532.59,2401.57 r0 top value=0.22uF
C85 "TPSD106K035R0125" 7343-31 4005.57,2659.68 r90 bottom value=10uF
C86 "CL05B104KO5NNNC" 0402 4138.89,2721.69 r90 bottom value=0.1uF
C87 "CL05B104KO5NNNC" 0402 4195.97,2752.59 r90 bottom value=0.1uF
C88 "GRM155Z71A225KE01D" FP-GRM155Z71A225KE01D_0402-MFG 3679.34,948.8 r0 bottom value=2.2µF
C89 "CGA1A2X7R1H331K030BA" 0201_033 3934.22,1314.47 r90 top value=330pF
C90 "CL05C360JB5NNNC" 0402 4290.46,2411.56 r180 bottom value=36pF
C91 "CL05C360JB5NNNC" 0402 4459.53,2403.49 r0 bottom value=36pF
C92 "CGA1A2X7R1H331K030BA" 0201_033 4028.12,1314.47 r90 top value=330pF
C93 "CGA1A2X7R1H331K030BA" 0201_033 3934.63,1236.19 r270 top value=330pF
C94 "CGA1A2X7R1H331K030BA" 0201_033 4028.12,1236.19 r270 top value=330pF
C95 "CGA1A2X7R1H331K030BA" 0201_033 3935.04,1180.48 r90 top value=330pF
C96 "CGA1A2X7R1H331K030BA" 0201_033 4028.94,1180.48 r90 top value=330pF
C97 "CGA1A2X7R1H331K030BA" 0201_033 3935.45,1102.19 r270 top value=330pF
C98 "CGA1A2X7R1H331K030BA" 0201_033 4028.94,1102.19 r270 top value=330pF
D1 "HSMF-C165" HSMF-C165_RG 3831.8,2403.77 r0 top value=Rg
D2 "NRVBA160T3G" SMA 1782.68,1348.07 r180 bottom value=60V
D3 "NRVBA160T3G" SMA 2511.89,1059.85 r180 bottom value=60V
D4 "APHHS1005SECK" APHHS1005_Orange 4713.89,2816.18 r90 top value=Orange
D5 "QTLP630C4TR" QTLP630C_Green 4717.63,2680.64 r90 top value=Green
D6 "HSMF-C165" HSMF-C165_RG 3834.25,2485.45 r0 top value=Rg
D7 "NRVBA160T3G" SMA 5120.07,2000.06 r270 top value=60V
FID1 "Fiducial" Fiducial10-20#1 5330.26,2477.28 r180 bottom
FID2 "Fiducial" Fiducial10-20#2 961.08,658.25 r270 top
FID3 "Fiducial" Fiducial10-20#3 970.26,587.59 r180 bottom
FID4 "Fiducial" Fiducial10-20#1 963.11,2439 r0 top
FID5 "Fiducial" Fiducial10-20#1 5309.76,2439.43 r0 top
FID6 "Fiducial" Fiducial10-20#1 970.26,2477 r180 bottom
H1 "NY PMS 440 0025 PH" "NY PMS 440 0025 PH" 5352.16,2785.43 r0 top
H2 "NY PMS 440 0025 PH" "NY PMS 440 0025 PH" 1084.25,2764.09 r0 top
H3 "NY PMS 440 0025 PH" "NY PMS 440 0025 PH" 1034.51,224.42 r0 top locked
H5 "1902E" Keystone_1902E 5334.56,275.59 r180 bottom
H6 "1902E" Keystone_1902E 5352.16,2785.43 r180 bottom
H7 "1902E" Keystone_1902E 1034.51,224.42 r180 bottom locked
H8 "1902E" Keystone_1902E 1084.25,2764.09 r180 bottom
J1 "" Sullins_PEC01SAAN 2668.9,1696.58 r180 top
J2 "PEC01SAAN" Sullins_PEC01SAAN 2806.69,1696.58 r180 top
J3 "TSW-102-07-G-D" TSW-102-07-G-D 1680.93,2589.6 r0 top
J4 "1502-2" Keystone1502-2#1 1283.68,702.29 r0 top
J5 "1502-2" Keystone1502-2#1 1288.8,2289.18 r0 top
J6 "PEC02SAAN" CONN_PEC02SAAN 2621.4,1206.85 r0 top
J7 "PEC02SAAN" CONN_PEC02SAAN 1946.43,2105.15 r180 top
J8 "PEC02SAAN" CONN_PEC02SAAN 1946.96,2236.42 r180 top
J9 "PEC02SAAN" CONN_PEC02SAAN 1945.91,2367.91 r180 top
J10 "PEC01SAAN" Sullins_PEC01SAAN 2573.43,1348.43 r0 top
J11 "PEC01SAAN" Sullins_PEC01SAAN 1738.71,2237.95 r0 top
J12 "PEC01SAAN" Sullins_PEC01SAAN 1741.17,2382.95 r0 top
J13 "PEC01SAAN" Sullins_PEC01SAAN 1738.71,2091.61 r0 top
J14 "ERM8-030-01-L-D-EM2-TR" Samtec_ERM8-030-01-L-D-EM2 -2.95,1492.13 r0 top
J15 "575-4" Keystone_575-4 1290.94,1110.23 r0 bottom
J16 "5-1814832-1" TE_5-1814832-1 3820.38,1794.13 r0 top
J17 "1-406541-1" TEC_1-406541-1 5293.17,1168.39 r90 top
J18 "ERF8-030-01-L-D-EM2-TR" Samtec_ERF8-030-01-x-D-EM2 3472.05,-2.36 r180 top
J19 "475890001" Molex_0475890001 5600,1941.71 r270 bottom
J20 "TSW-102-07-G-D" TSW-102-07-G-D 1680.93,2863.39 r0 top
J21 "575-4" Keystone_575-4 1290.13,1859.89 r0 bottom
J22 "HTSW-121-07-G-T" Samtec_HTSW-121-07-x-T 532.28,1454.36 r0 top
J23 "PEC02SAAN" CONN_PEC02SAAN 5512.8,2244.41 r90 top
J24 "1502-2" Keystone1502-2#2 5380.51,506.21 r0 top
L1 "SRP5030T-100M" SRP5030T 2227.96,1075 r0 bottom value=10uH
LD1 "QTLP630C4TR" QTLP630C_Green 2965.16,817.49 r270 top value=Green
LD2 "QTLP630C4TR" QTLP630C_Green 5082.61,2272.59 r0 top value=Green
LD3 "QTLP630C4TR" QTLP630C_Green 2304.5,1056.57 r270 top value=Green
LD4 "QTLP630C4TR" QTLP630C_Green 2294.65,756.52 r270 top value=Green
LD5 "QTLP630C4TR" QTLP630C_Green 2294.65,454.21 r270 top value=Green
LD6 "QTLP630C4TR" QTLP630C_Green 2304.27,216.26 r270 top value=Green
Logo1 "CE Mark" CE_Mark_5mm 1894.66,495.55 r180 bottom
Logo2 "Texas Instruments" TI_Stacked_Overlay_Small 3585.98,535.78 r0 top
Logo3 "FCC disclaimer" FCC_disclaimer 5926.77,679.13 r90 bottom
Logo4 "WEEE logo" WEEE_Minimum 1605.01,535.78 r180 bottom
R1 "CRCW0603200KJNEA" 0603 3160.92,1498.03 r90 bottom value=200k
R2 "CRCW0603200KJNEA" 0603 2601.97,2098.43 r90 bottom value=200k
R3 "ERJ-3GEYJ222V" 0603 3831.8,2611.74 r90 bottom value=2.2k
R4 "ERJ-3GEYJ222V" 0603 3093.57,2588.81 r0 bottom value=2.2k
R5 "CRCW0603102RFKEA" 0603 2268.96,2581.02 r0 bottom value=102
R6 "ERJ-3GEY0R00V" 0603 3682.06,2519.98 r0 bottom value=0
R7 "CRCW0603330RJNEA" 0603 3024.67,2519.91 r0 bottom value=330
R8 "ERJ-2GE0R00X" 0402 3066.8,2460.63 r0 top value=0
R9 "ERJ-2GE0R00X" 0402 3015.35,2348.43 r270 top value=0
R10 "ERJ-2GE0R00X" 0402 3455.03,2242.92 r90 bottom value=0
R11 "ERJ-2GE0R00X" 0402 3376.4,2253.94 r90 bottom value=0
R12 "CRCW060324K9FKEA" 0603 3359.24,1802 r180 bottom value=24.9k
R13 "CRCW04020000Z0ED" 0402 3452.37,1736.39 r90 top value=0
R14 "RC0201JR-07470RL" 0201 3751.57,2387.06 r180 top value=470
R15 "RC0201JR-07470RL" 0201 3751.57,2418.06 r180 top value=470
R16 "RC0201JR-07470RL" 0201 3499.32,2473.62 r270 top value=470
R17 "RC0201JR-07470RL" 0201 3465.59,2482.84 r270 top value=470
R18 "CRCW02010000Z0ED" 0201 3053.74,1479.53 r270 top value=0
R19 "CRCW02010000Z0ED" 0201 3037.71,1552.79 r90 top value=0
R20 "CRCW04021K40FKED" 0402 3153.55,1726.18 r0 bottom value=1.40k
R21 "CRCW04021M00FKED" 0402 3102.95,1781.5 r180 bottom value=1.00Meg
R22 "CRCW040247K0JNED" 0402 4392.82,1841.77 r270 top value=47k
R23 "CRCW04020000Z0ED" 0402 2964.17,1917.36 r0 top value=0
R24 "RMCF0603ZT0R00" 0603 1972.83,1200.05 r0 bottom value=0
R25 "CRCW0603100KFKEA" 0603 1837.78,1200.05 r0 bottom value=100k
R26 "CRCW060324K9FKEA" 0603 1803.78,1100.25 r90 bottom value=24.9k
R27 "ERJ-3GEY0R00V" 0603 2737.05,1059.61 r90 bottom value=0
R28 "CRCW0402100KDHEDP" 0402 2942.16,1207.64 r180 bottom value=100k
R29 "CRCW0402470RJNED" 0402 3038.98,887.19 r90 top value=470
R30 "ERJ-3GEY0R00V" 0603 2739.8,891.29 r90 bottom value=0
R31 "CRCW0402165KFKED" 0402 3048.75,1078 r180 bottom value=165k
R32 "ERJ-3GEY0R00V" 0603 5113.3,2193.4 r90 bottom value=0
R33 "CRCW0402100KDHEDP" 0402 5113.3,2321.33 r270 bottom value=100k
R34 "CRCW0402470RJNED" 0402 4991.1,2333.36 r0 top value=470
R35 "ERJ-3GEY0R00V" 0603 5040.28,2188.76 r270 bottom value=0
R36 "CRCW0402165KFKED" 0402 5188.5,2394.26 r270 bottom value=165k
R37 "CRCW02010000Z0ED" 0201 3682.68,1285.05 r180 top value=0
R38 "RC0402JR-070RL" 0402 4375.6,2389.05 r90 bottom value=0
R39 "RC0402FR-071ML" 0402 3859.36,1347.04 r0 top value=1.00Meg
R40 "CRCW02010000Z0ED" 0201 3763.1,1349.64 r0 top value=0
R41 "CRCW06030000Z0EA" 0603 4003.95,983.48 r270 top value=0
R42 "CRCW02010000Z0ED" 0201 3750.11,1362.63 r270 top value=0
R43 "CRCW080575R0FKEA" 0805_HV 4807.75,1158.23 r180 bottom value=75.0
R44 "CRCW080575R0FKEA" 0805_HV 4807.75,1268.39 r180 bottom value=75.0
R45 "CRCW080575R0FKEA" 0805_HV 4981.01,1223.69 r0 bottom value=75.0
R46 "CRCW080575R0FKEA" 0805_HV 4981.01,1116.08 r0 bottom value=75.0
R47 "CRCW04022K20JNED" 0402 3604.64,1384.29 r0 top value=2.2k
R48 "CRCW04026K49FKED" 0402 3536.52,1461.84 r270 bottom value=6.49k
R49 "RC0201JR-07470RL" 0201 2583.3,682.71 r0 top value=470
R50 "ERJ-1GN0R00C" 0201 3694.3,929.12 r180 top value=0
R51 "HVC2010-10MJT3" 2010 4548.75,431.19 r180 bottom value=10Meg
R52 "5113" FP-5113_0402-MFG 3981.11,1301.48 r0 top value=0
R53 "CRCW0402470RJNED" 0402 2379.54,1082.17 r90 top value=470
R54 "RMCF0402FT1K50" 0402 2383.24,693.87 r90 top value=1.50k
R55 "CRCW0402470RJNED" 0402 2383.24,810.01 r90 top value=470
R56 "RMCF0402FT1K50" 0402 2379.54,961.56 r270 top value=1.50k
R57 "CRCW0402470RJNED" 0402 2382.01,512.16 r90 top value=470
R58 "CRCW0402470RJNED" 0402 2379.37,232.01 r90 top value=470
R59 "RMCF0402FT1K50" 0402 2380.91,395.91 r90 top value=1.50k
R60 "RMCF0402FT1K50" 0402 2379.37,119.3 r90 top value=1.50k
R61 "CRCW04021K50FKED" 0402 4923.49,2088.29 r180 top value=1.50k
R62 "CRCW040210K0JNED" 0402 4616.6,2245.23 r0 top value=10k
R63 "CRCW040227R0JNED" 0402 3571.96,1605.55 r0 bottom value=27
R64 "CRCW040222R0JNED" 0402 5118.22,2018.31 r180 bottom value=22
R65 "CRCW040222R0JNED" 0402 5117.8,1959.88 r180 bottom value=22
R66 "CRCW040227R0JNED" 0402 3571.96,1556.33 r0 bottom value=27
R67 "CRCW040222R0JNED" 0402 4432.19,2127.2 r0 top value=22
R68 "CRCW040222R0JNED" 0402 4432.19,2077.99 r0 top value=22
R69 "CRCW040215K0FKED" 0402 4310.15,1979.56 r180 top value=15.0k
R70 "CRCW040215K0FKED" 0402 4201.88,1979.56 r0 top value=15.0k
R71 "CRCW040222R0JNED" 0402 4416.45,1999.44 r0 bottom value=22
R72 "CRCW040222R0JNED" 0402 4416.45,1947.88 r0 bottom value=22
R73 "CRCW040215K0FKED" 0402 4333.77,1910.66 r90 bottom value=15.0k
R74 "CRCW040215K0FKED" 0402 4333.77,2022.87 r270 bottom value=15.0k
R75 "CRCW040233R0JNED" 0402 5291.29,1841.72 r180 bottom value=33
R76 "CRCW040227R0JNED" 0402 4304.24,2137.04 r270 bottom value=27
R77 "CRCW04021K40FKED" 0402 4579.08,2416.96 r0 bottom value=1.40k
R78 "CRCW02010000Z0ED" 0201 3425.11,1333.89 r180 top value=0
R79 "CRCW040247K0JNED" 0402 4743.22,2289.18 r0 top value=47k
R80 "CRCW040227R0JNED" 0402 4255.03,2137.04 r270 bottom value=27
R81 "CRCW04021M00FKED" 0402 4229.37,2284.68 r0 bottom value=1.00Meg
R82 "CRCW040215K0FKED" 0402 4583.77,1812.24 r90 top value=15.0k
R83 "CRCW040215K0FKED" 0402 4638.3,1811.29 r90 top value=15.0k
R84 "CRCW040215K0FKED" 0402 4695.08,1839.04 r90 top value=15.0k
R85 "CRCW040215K0FKED" 0402 4748.39,1839.04 r90 top value=15.0k
R86 "CRCW0402470RJNED" 0402 4652.04,2855.55 r90 top value=470
R87 "CRCW0402470RJNED" 0402 4638.26,2658.7 r90 top value=470
R88 "CRCW06030000Z0EA" 0603 3264.57,1334.18 r0 bottom value=0
R89 "CRCW0402240KJNED" 0402 4234.13,2291.28 r0 top value=240k
R90 "CRCW0402220KJNED" 0402 4017.32,2566.49 r90 top value=220k
R91 "CRCW0402150KJNED" 0402 4179.55,2345.03 r0 top value=150k
R92 "CRCW0402220KJNED" 0402 4077.86,2496.07 r90 top value=220k
R93 "CRCW040247K0JNED" 0402 4294.4,2642.95 r90 top value=47k
R94 "RC0402JR-070RL" 0402 4799.52,2446.23 r270 bottom value=0
R95 "RC0402JR-070RL" 0402 4857.39,2502.28 r270 bottom value=0
R96 "CRCW02010000Z0ED" 0201 3554.92,1015.32 r270 top value=0
R97 "CRCW02010000Z0ED" 0201 3526.38,992.4 r270 top value=0
R98 "CRCW02010000Z0ED" 0201 3327.39,1127.13 r180 top value=0
R99 "CRCW02010000Z0ED" 0201 3304.53,1181.1 r180 top value=0
R100 "CRCW02010000Z0ED" 0201 3442.63,1447.08 r180 top value=0
R101 "CRCW02010000Z0ED" 0201 3436.13,1409.68 r180 top value=0
R102 "CRCW02010000Z0ED" 0201 3431.6,1372.47 r180 top value=0
R103 "CRCW02010000Z0ED" 0201 3309.06,1265.91 r180 top value=0
R104 "CRCW02010000Z0ED" 0201 3338.69,1226.54 r180 top value=0
R105 "CRCW02012K20JNED" 0201M 3694.3,978.33 r0 top value=2.2k
R106 "CRCW04021K50FKED" 0402 4853.04,1834.48 r90 top value=1.50k
R107 "CRCW02010000Z0ED" 0201 3737.12,1349.64 r180 top value=0
R108 "CRCW02010000Z0ED" 0201 2501.57,449.96 r270 bottom value=0
R109 "ERJ-2GE0R00X" 0402 2559.65,1814.44 r180 top value=0
R110 "ERJ-2GE0R00X" 0402 2615.75,1897.87 r180 top value=0
R111 "5113" FP-5113_0402-MFG 3981.38,1249.18 r0 top value=0
R112 "5113" FP-5113_0402-MFG 3981.93,1167.48 r0 top value=0
R113 "5113" FP-5113_0402-MFG 3982.2,1115.18 r0 top value=0
R114 "CRCW04022K49FKED" 0402 3260.1,1279.05 r0 bottom value=2.49k
R115 "RMCF0402FT1K50" 0402 3338.19,1212.09 r90 bottom value=1.50k
S1 "218-4LPST" SW_218-4LPST 1952.36,1554.56 r180 top
S2 "KSR221GLFS" KSR 4076.38,1682.32 r90 top
S3 "KSR221GLFS" KSR 2727.95,615.39 r270 top
SH-J1 "M7582-05" Harwin_M7582-05 1947.23,2365.42 r180 top
SH-J2 "M7582-05" Harwin_M7582-05 1948.38,2235.26 r180 top
SH-J3 "M7582-05" Harwin_M7582-05 1945.63,2106.3 r180 top
SH-J4 "M7582-05" Harwin_M7582-05 2622.67,1204.47 r180 top
T2 "HX1188FNLT" Pulse_HX1188FNLT 4528.49,1211.54 r0 top value=350uH
U1 "SN74LVC1G04QDBVRQ1" DBV0005A_N 2300.46,2374.33 r180 bottom
U2 "LSF0102DQER" DQE0008A 3082.28,1472.05 r90 bottom
U3 "LSF0102DQER" DQE0008A 2633.46,1931.33 r180 bottom
U4 "HFBR-2412TZ" HFBR-x41xTZ 3648.34,2760.17 r90 top
U5 "HFBR-2412TZ" HFBR-x41xTZ 2945.28,2760.17 r90 top
U6 "HFBR-1412PZ" HFBR-x41xZ 2240.15,2756.92 r90 top
U7 "TMUX1219DCKR" DCK0006A_N 2767.32,2420.87 r270 bottom
U8 "MSP430F5529IPN" PN0080A_N 3351.68,2138.45 r180 top
U9 "TMUX1219DCKR" DCK0006A_N 3257.7,2303.15 r270 bottom
U10 "LMR33620ARNXT" RNX0012B 1999.4,1075 r90 bottom
U11 "TL5209DR" D0008A_N 2894.53,969.06 r270 bottom
U12 "TL5209DR" D0008A_N 5306.69,2236.22 r0 bottom
U13 "TPD4E05U06DQAR" DQA0010A 4138.68,1213.15 r0 top
U14 "DP83826A" RHB0032M-MFG 3527.82,1197.01 r180 top
U15 "TUSB2046BIRHBT" RHB0032E 4723.73,2093.93 r270 top
U16 "MSP430F5528IRGCR" RGC0064B 4420.16,2675.51 r0 bottom
XF1 "0031.7701.11" Schurter_0031-7701-11 966.14,1200.79 r270 bottom
XTAL1 "ECS-250-12-33Q-JES-TR" ECS_ECS-33Q 3859.84,1456.3 r0 top
Y1 "ECS-240-20-33-DU-TR" ECS_ECX-32 3346.12,1700.96 r270 top
Y2 "CSTCR6M00G53Z-R0" Murata_CSTCR_G 4944.01,1872.28 r270 top
Y3 "ECS-240-20-33-DU-TR" ECS_ECX-32 4157.89,2380.47 r270 bottom
ZZ1 "These assemblies are ESD sensitive, ESD precautions shall be observed." AssemblyNote 265.31,3966.91 r0 top
ZZ2 "These assemblies must be clean and free from flux and all contaminants. Use of no clean flux is not acceptable." AssemblyNote 265.31,3878.35 r0 top
ZZ3 "These assemblies must comply with workmanship standards IPC-A-610 Class 2, unless otherwise specified." AssemblyNote 265.31,3789.8 r0 top
ZZ4 "Add F1 fuse into XF1 fuse holder" AssemblyNote 256.84,3619.33 r0 top

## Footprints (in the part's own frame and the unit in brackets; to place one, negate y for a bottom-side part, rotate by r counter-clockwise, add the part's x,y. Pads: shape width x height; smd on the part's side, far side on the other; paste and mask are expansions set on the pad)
0201 [mm] "Data from Kemet datasheet CC101_COM dated 7/28/11"
  rect 0.46x0.42 smd mask+0.048: 1(-0.33,0) 2(0.33,0)
  body extent -0.31,-0.16 0.31,0.16, height 0.26
0201_033 [mm] "SMD, 2-Leads, Height 0.33mm"
  rect 0.46x0.42 smd mask+0.048: 1(-0.33,0) 2(0.33,0)
  body extent -0.31,-0.16 0.31,0.16, height 0.33
0201M [mm] "Data from Kemet datasheet CC101_COM dated 7/28/11"
  rect 0.56x0.52 smd mask+0.048: 1(-0.38,0) 2(0.38,0)
  body extent -0.31,-0.16 0.31,0.16, height 0.26
0402 [mm] "0402 from SM-752 data"
  rect 0.8x0.6 smd: 1(-0.6,0) 2(0.6,0)
  silkscreen extent -1.22,-0.52 1.22,0.52, body extent -0.55,-0.3 0.55,0.3, height 0.6
0603 [mm] "0603 from SM-752 data"
  rect 1x0.95 smd: 1(-0.8,0) 2(0.8,0)
  silkscreen extent -1.52,-0.69 1.52,0.69, body extent -0.87,-0.47 0.87,0.47, height 1
0805_HV [mil] "0805 with 30mil clearance between pads"
  rect 50x63 smd: 1(-40,0) 2(40,0)
  silkscreen extent -74,-40 74,40, body extent -43,-29 43,29, height 57
1206_180 [mm] "1206_180"
  rect 1.1x1.6 smd: 1(-1.7,0) 2(1.7,0)
  silkscreen extent -0.9,-1 0.9,1, body extent -1.75,-0.95 1.75,0.95, height 1.8
1210_270 [mm] "1210"
  rect 1.3x2.7 smd: 1(-1.45,0) 2(1.45,0)
  silkscreen extent -2.32,-1.57 2.32,1.57, body extent -1.7,-1.35 1.7,1.35, height 2.7
1210_280 [mm] "SMD, 2-Leads, Body 3.6x2.8mm, Height 2.8mm"
  rect 1.1x2.2 smd: 1(-1.65,0) 2(1.65,0)
  silkscreen extent -0.84,-1.4 0.84,1.4, body extent -1.8,-1.4 1.8,1.4, height 2.8
1812_254 [mm] "SMD, 2-Leads, Body 4.8x3.4mm"
  rect 1.6x3.4 smd: 1(-2,0) 2(2,0)
  silkscreen extent -0.8,-1.7 0.8,1.7, body extent -2.4,-1.7 2.4,1.7, height 2.54
2010 [mm] "Chip Capacitor, Body 5.08x2.54mm, IPC Medium Density"
  rect 1.6x2.7 smd: 1(-2.3,0) 2(2.3,0)
  silkscreen extent -3.42,-1.65 3.42,1.65, body extent -2.73,-1.45 2.73,1.45, height 1.66
7343-31 [mm] "Medium Density based on Kemet T495 dimensions"
  rect 2.55x2.45 smd: 1(-3.025,0) 2(3.025,0)
  silkscreen extent -4.56,-2.3 3.8,2.3, body extent -3.8,-2.3 3.8,2.3, height 3.1
APHHS1005_Orange [mm] "SMD, 2-Leads, Body 1x0.5mm"
  rrect20% 0.7x0.5 smd: 1(-0.45,0) 2(0.45,0)
  silkscreen extent -1.2,-0.65 0.8,0.65, body extent -0.5,-0.25 0.5,0.25, height 0.5
AssemblyNote [mil] "Assembly Note"
CAPSMT_62_HA0 [mm] "8 x 10mm:  Chemi-Con HA0"
  rect 4.2x2.2 smd: 1(-3.65,0) 2(3.65,0)
  silkscreen extent -4.25,-4.25 4.25,4.25, body extent -4.25,-4.25 4.25,4.25, height 10.5
CE_Mark_5mm [mil] "Minimum text height for CE Mark"
  silkscreen extent -138,-98 138,98
CONN_PEC02SAAN [mm] "SULLINS"
  rrect7% 1.5x1.5 hole 1.016: 1(-1.27,0)
  round 1.5 hole 1.016: 2(1.27,0)
  silkscreen extent -2.54,-1.52 2.54,1.27, body extent -2.54,-1.27 2.54,1.27, height 8.38
D0008A_N [mm] "SOIC, 8-Leads, Body 4.9x3.9mm, Pitch 1.27mm, IPC Medium Density"
  oval 1.45x0.6 smd: 1(-2.725,1.905) 2(-2.725,0.635) 3(-2.725,-0.635) 4(-2.725,-1.905) 5(2.725,-1.905) 6(2.725,-0.635) 7(2.725,0.635) 8(2.725,1.905)
  silkscreen extent -3.3,-2.5 0.9,2.5, body extent -3,-2.45 3,2.45, height 1.63
DBV0005A_N [mm] "SOT23, 5-Leads, Body 2.9x1.6mm, Pitch 0.95mm, Lead Span 2.8mm, IPC Medium Density"
  rrect17% 1x0.6 smd: 1(-1.375,0.95) 2(-1.375,0) 3(-1.375,-0.95) 4(1.375,-0.95) 5(1.375,0.95)
  silkscreen extent -1.63,-1.55 0.38,1.55, body extent -1.42,-1.46 1.42,1.46, height 1.09
DCK0006A_N [mm] "SOT23, 6-Leads, Body 2x1.3mm, Pitch 0.65mm, Lead Span 2.1mm, IPC Medium Density"
  rrect25% 0.85x0.4 smd: 1(-1.125,0.65) 2(-1.125,0) 3(-1.125,-0.65) 4(1.125,-0.65) 5(1.125,0) 6(1.125,0.65)
  silkscreen extent -1.5,-1.09 0.51,1.09, body extent -1.14,-1 1.14,1, height 0.95
DQA0010A [mm] "SON, 10-Leads, Body 1x2.5mm, Pitch 0.5mm, TI Recommended"
  rrect50% 0.565x0.2 smd: 1(-0.417,1) 2(-0.417,0.5) 4(-0.417,-0.5) 5(-0.417,-1) 6(0.417,-1) 7(0.417,-0.5) 9(0.417,0.5) 10(0.417,1)
  rrect28% 0.565x0.36 on Top Paste: 3(-0.417,0) 8(0.417,0)
  rrect25% 0.565x0.4 smd paste-0.2: 3(-0.417,0) 8(0.417,0)
  silkscreen extent -0.67,-1.45 0.55,1.45, body extent -0.55,-1.3 0.55,1.3, height 0.56
DQE0008A [mm] "SON, 8-Leads, Body 1.4x1mm, Pitch 0.35mm, TI Recommended"
  rect 0.6x0.16 smd: 1(-0.4,0.525)
  rect 0.5x0.16 smd: 2(-0.45,0.175) 3(-0.45,-0.175) 4(-0.45,-0.525) 5(0.45,-0.525) 6(0.45,-0.175) 7(0.45,0.175) 8(0.45,0.525)
  silkscreen extent -0.7,-0.85 0.4,0.85, body extent -0.53,-0.72 0.53,0.73, height 0.41
ECS_ECS-33Q [mm] "SMD, 4-Leads, Body 2.5x3.2mm"
  rrect9% 1.1x1.3 smd: 1(-0.9,1.15) 2(-0.9,-1.15) 3(0.9,-1.15) 4(0.9,1.15)
  silkscreen extent -1.75,0.6 -1.75,1.7, body extent -1.3,-1.65 1.3,1.65, height 0.81
ECS_ECX-32 [mm] "SMD, 4-Leads, Body 3.2x2.5mm"
  rect 1.1x1.3 smd: 1(-0.9,1.15) 2(-0.9,-1.15) 3(0.9,-1.15) 4(0.9,1.15)
  silkscreen extent -1.81,-0.2 1.3,1.21, body extent -1.25,-1.6 1.25,1.6, height 0.81
FCC_disclaimer [mil]
Fiducial10-20#1 [mm]
  round 1 smd mask+0.5: 1(0,0)
  Top Layer keep-out circle w1.178: c0,0 r0.5
Fiducial10-20#2 [mm]
  round 1 smd mask+0.5: 1(0,0.052)
  Top Layer keep-out circle w1.178: c0,0 r0.5
Fiducial10-20#3 [mm]
  round 1 smd mask+0.5: 1(0.108,0)
  Top Layer keep-out circle w1.178: c0,0 r0.5
FP-5113_0402-MFG [mm]
  rrect25% 0.4x0.6 smd paste+0 mask+0: 1(-0.45,0) 2(0.45,0)
  silkscreen extent -0.57,-0.67 0.57,0.67, body extent -0.75,-0.42 0.75,0.42, height 0.25
FP-GRM155Z71A225KE01D_0402-MFG [mm]
  rrect22% 0.45x0.6 smd paste+0 mask+0: 1(-0.475,0) 2(0.475,0)
  silkscreen extent -0.58,-0.73 0.58,0.72, body extent -0.5,-0.25 0.5,0.25, height 0.65
Harwin_M7582-05 [mil] "Single Operation 2.54mm Pitch Open Top Jumper Socket"
  body extent -98,-47 98,47, height 236
HFBR-x41xTZ [mm] "TH, 8-Leads, Body 12.7x27.2mm"
  rrect50% 1.35x1.35 hole 0.9: 1(-1.27,3.81)
  round 1.125 hole 0.75: 2(-1.27,1.27) 3(-1.27,-1.27) 6(1.27,-1.27) 7(1.27,1.27)
  round 1.35 hole 0.9: 4(-1.27,-3.81) 5(1.27,-3.81) 8(1.27,3.81)
  body extent -5.08,-6.35 22.12,6.35, height 10.2
HFBR-x41xZ [mm] "TH, 8-Leads, Body 12.7x27.2mm"
  rrect50% 1.35x1.35 hole 0.9: 1(-1.27,3.81)
  round 1.125 hole 0.75: 2(-1.27,1.27) 3(-1.27,-1.27) 6(1.27,-1.27) 7(1.27,1.27)
  round 1.35 hole 0.9: 4(-1.27,-3.81) 5(1.27,-3.81) 8(1.27,3.81)
  body extent -5.08,-6.35 22.12,6.35, height 10.2
HSMF-C165_RG [mm] "SMD, 4-Leads, Body 1.6x0.8mm"
  rect 0.7x0.4 smd: 1(-0.65,0.35) 2(-0.65,-0.35) 3(0.65,0.35) 4(0.65,-0.35)
  silkscreen extent -1,-0.8 1.5,0.8, body extent -0.85,-0.45 0.85,0.45, height 0.51
Keystone1502-2#1 [mm] "Double Turret"
  round 3.5 hole 2.5: 1(0,0)
  silkscreen extent -2.3,-2.3 2.3,2.3, body extent -1.6,-1.6 1.59,1.6, height 5.62
Keystone1502-2#2 [mm] "Double Turret"
  round 3.5 smd far side: 1(0,0)
  silkscreen extent -2.3,-2.3 2.3,2.3, body extent -1.6,-1.6 1.59,1.6, height 5.62
Keystone_575-4 [mm] "Banana Jack"
  round 10 hole 5.45: 1(0,0)
  body extent -3.98,-3.95 3.92,3.94, height 2.36
Keystone_1902E [mil] "Hex Standoff, 4-40 threaded, nylon"
  round 1 on Mech4: 0(0,0)
  body extent -145,-126 146,126, height 1001
KSR [mm] "C&K Components SPST switch"
  rect 1.5x1.4 smd: 1(-3.25,0) 2(3.25,0)
  silkscreen extent -3.2,-2 3.2,2, body extent -3,-1.9 3,1.9, height 2.65
Molex_0475890001 [mm] "Molex"
  rrect25% 0.4x1.35 smd: 1(-1.3,4.125) 2(-0.65,4.125) 3(0,4.125) 4(0.65,4.125) 5(1.3,4.125)
  oval 1.05x1.3 hole 0.7 slot 0.85 at 90 deg: 6(2.225,4.45) 11(-2.225,4.45)
  oval 0.8x2 hole 0.6 slot 1.3 at 90 deg: 7(4.175,1.45) 10(-4.175,1.45)
  rrect6% 1.8x2 smd: 8(1.15,1.45) 9(-1.15,1.45)
  Top Layer region: 2.6,0.45 2.6,2.45 4.175,2.45 4.175,0.45
  Top Layer region: -4.175,0.45 -4.175,2.45 -2.6,2.45 -2.6,0.45
  silkscreen extent -3.75,2.85 3.75,4.3, body extent -4.32,-1.3 4.33,4.59, height 2.81
Murata_CSTCR_G [mm] "Murata"
  rect 0.4x2.6 smd: 1(-1.5,0) 2(0,0) 3(1.5,0)
  Top Layer region: -0.4,0.8 0.4,0.8 0.4,1.3 -0.4,1.3
  Top Layer region: -0.4,-1.301 -0.4,-0.801 0.4,-0.801 0.4,-1.301
  Top Layer region: -1.9,0.8 -1.1,0.8 -1.1,1.3 -1.9,1.3
  Top Layer region: -1.9,-1.301 -1.9,-0.801 -1.1,-0.801 -1.1,-1.301
  Top Layer region: 1.1,0.8 1.9,0.8 1.9,1.3 1.1,1.3
  Top Layer region: 1.1,-1.301 1.1,-0.801 1.9,-0.801 1.9,-1.301
  body extent -2.25,-1 2.25,1, height 1.16
"NY PMS 440 0025 PH" [mm] "4-40 nylon screw and mounting hole"
  round 8 hole 3.2: 1(0,0)
  body extent -3.3,-3.3 3.3,3.3, height 2.69
PN0080A_N [mm] "QFP, 80-Leads, Body 12x12mm, Pitch 0.5mm, IPC Medium Density"
  oval 1.45x0.3 smd: 1(-6.725,4.75) 2(-6.725,4.25) 3(-6.725,3.75) 4(-6.725,3.25) 5(-6.725,2.75) 6(-6.725,2.25) 7(-6.725,1.75) 8(-6.725,1.25) 9(-6.725,0.75) 10(-6.725,0.25) 11(-6.725,-0.25) 12(-6.725,-0.75) 13(-6.725,-1.25) 14(-6.725,-1.75) 15(-6.725,-2.25) 16(-6.725,-2.75) 17(-6.725,-3.25) 18(-6.725,-3.75) 19(-6.725,-4.25) 20(-6.725,-4.75) 41(6.725,-4.75) 42(6.725,-4.25) 43(6.725,-3.75) 44(6.725,-3.25) 45(6.725,-2.75) 46(6.725,-2.25) 47(6.725,-1.75) 48(6.725,-1.25) 49(6.725,-0.75) 50(6.725,-0.25) 51(6.725,0.25) 52(6.725,0.75) 53(6.725,1.25) 54(6.725,1.75) 55(6.725,2.25) 56(6.725,2.75) 57(6.725,3.25) 58(6.725,3.75) 59(6.725,4.25) 60(6.725,4.75)
  oval 0.3x1.45 smd: 21(-4.75,-6.725) 22(-4.25,-6.725) 23(-3.75,-6.725) 24(-3.25,-6.725) 25(-2.75,-6.725) 26(-2.25,-6.725) 27(-1.75,-6.725) 28(-1.25,-6.725) 29(-0.75,-6.725) 30(-0.25,-6.725) 31(0.25,-6.725) 32(0.75,-6.725) 33(1.25,-6.725) 34(1.75,-6.725) 35(2.25,-6.725) 36(2.75,-6.725) 37(3.25,-6.725) 38(3.75,-6.725) 39(4.25,-6.725) 40(4.75,-6.725) 61(4.75,6.725) 62(4.25,6.725) 63(3.75,6.725) 64(3.25,6.725) 65(2.75,6.725) 66(2.25,6.725) 67(1.75,6.725) 68(1.25,6.725) 69(0.75,6.725) 70(0.25,6.725) 71(-0.25,6.725) 72(-0.75,6.725) 73(-1.25,6.725) 74(-1.75,6.725) 75(-2.25,6.725) 76(-2.75,6.725) 77(-3.25,6.725) 78(-3.75,6.725) 79(-4.25,6.725) 80(-4.75,6.725)
  silkscreen extent -6.85,-5.6 5.6,5.6, body extent -7,-7 7,7, height 1.56
Pulse_HX1188FNLT [mm] "SMD, 16-Leads, Body 12.7x9.09mm, Pitch 1.27mm"
  rect 1.65x0.76 smd: 1(-4.255,4.445) 2(-4.255,3.175) 3(-4.255,1.905) 4(-4.255,0.635) 5(-4.255,-0.635) 6(-4.255,-1.905) 7(-4.255,-3.175) 8(-4.255,-4.445) 9(4.255,-4.445) 10(4.255,-3.175) 11(4.255,-1.905) 12(4.255,-0.635) 13(4.255,0.635) 14(4.255,1.905) 15(4.255,3.175) 16(4.255,4.445)
  silkscreen extent -4.87,-6.42 4.61,6.42, body extent -4.65,-6.42 4.65,6.42, height 6.13
QTLP630C_Green [mm] "SMT, 2-Leads, Body 2x1.25mm"
  rect 1.2x1.2 smd: 1(-1.05,0) 2(1.05,0)
  silkscreen extent -0.15,-0.8 2.15,0.8, body extent -1.1,-0.73 1.1,0.73, height 1.22
RGC0064B [mm] "VQFN-64"
  rrect42% 0.6x0.24 smd mask+0.07: 1(-4.4,3.75) 2(-4.4,3.25) 3(-4.4,2.75) 4(-4.4,2.25) 5(-4.4,1.75) 6(-4.4,1.25) 7(-4.4,0.75) 8(-4.4,0.25) 9(-4.4,-0.25) 10(-4.4,-0.75) 11(-4.4,-1.25) 12(-4.4,-1.75) 13(-4.4,-2.25) 14(-4.4,-2.75) 15(-4.4,-3.25) 16(-4.4,-3.75) 33(4.4,-3.75) 34(4.4,-3.25) 35(4.4,-2.75) 36(4.4,-2.25) 37(4.4,-1.75) 38(4.4,-1.25) 39(4.4,-0.75) 40(4.4,-0.25) 41(4.4,0.25) 42(4.4,0.75) 43(4.4,1.25) 44(4.4,1.75) 45(4.4,2.25) 46(4.4,2.75) 47(4.4,3.25) 48(4.4,3.75)
  rrect42% 0.24x0.6 smd mask+0.07: 17(-3.75,-4.4) 18(-3.25,-4.4) 19(-2.75,-4.4) 20(-2.25,-4.4) 21(-1.75,-4.4) 22(-1.25,-4.4) 23(-0.75,-4.4) 24(-0.25,-4.4) 25(0.25,-4.4) 26(0.75,-4.4) 27(1.25,-4.4) 28(1.75,-4.4) 29(2.25,-4.4) 30(2.75,-4.4) 31(3.25,-4.4) 32(3.75,-4.4) 49(3.75,4.4) 50(3.25,4.4) 51(2.75,4.4) 52(2.25,4.4) 53(1.75,4.4) 54(1.25,4.4) 55(0.75,4.4) 56(0.25,4.4) 57(-0.25,4.4) 58(-0.75,4.4) 59(-1.25,4.4) 60(-1.75,4.4) 61(-2.25,4.4) 62(-2.75,4.4) 63(-3.25,4.4) 64(-3.75,4.4)
  rrect2% 4.25x4.25 smd paste-2.112: 65(0,0)
  body extent -4.5,-4.5 4.5,4.5, height 1
RHB0032E [mm] "QFN, 32-Leads, Body 5x5mm, Pitch 0.5mm, Thermal Pad 3.45x3.45mm, TI Recommended"
  rrect40% 0.6x0.25 smd: 1(-2.4,1.75) 2(-2.4,1.25) 3(-2.4,0.75) 4(-2.4,0.25) 5(-2.4,-0.25) 6(-2.4,-0.75) 7(-2.4,-1.25) 8(-2.4,-1.75) 17(2.4,-1.75) 18(2.4,-1.25) 19(2.4,-0.75) 20(2.4,-0.25) 21(2.4,0.25) 22(2.4,0.75) 23(2.4,1.25) 24(2.4,1.75)
  rrect40% 0.25x0.6 smd: 9(-1.75,-2.4) 10(-1.25,-2.4) 11(-0.75,-2.4) 12(-0.25,-2.4) 13(0.25,-2.4) 14(0.75,-2.4) 15(1.25,-2.4) 16(1.75,-2.4) 25(1.75,2.4) 26(1.25,2.4) 27(0.75,2.4) 28(0.25,2.4) 29(-0.25,2.4) 30(-0.75,2.4) 31(-1.25,2.4) 32(-1.75,2.4)
  rrect3% 3.45x3.45 smd paste-1.725: 33(0,0)
  rrect7% 1.49x1.49 on Top Paste: ""(-0.845,0.845) ""(-0.845,-0.845) ""(0.845,0.845) ""(0.845,-0.845)
  silkscreen extent -2.72,-2.73 2.72,2.73, body extent -2.57,-2.57 2.58,2.58, height 1.01
RHB0032M-MFG [mm] "Recommended Land Pattern"
  rrect40% 0.6x0.25 smd paste+0 mask+0: 1(-2.4,1.75) 2(-2.4,1.25) 3(-2.4,0.75) 4(-2.4,0.25) 5(-2.4,-0.25) 6(-2.4,-0.75) 7(-2.4,-1.25) 8(-2.4,-1.75) 17(2.4,-1.75) 18(2.4,-1.25) 19(2.4,-0.75) 20(2.4,-0.25) 21(2.4,0.25) 22(2.4,0.75) 23(2.4,1.25) 24(2.4,1.75)
  rrect40% 0.25x0.6 smd paste+0 mask+0: 9(-1.75,-2.4) 10(-1.25,-2.4) 11(-0.75,-2.4) 12(-0.25,-2.4) 13(0.25,-2.4) 14(0.75,-2.4) 15(1.25,-2.4) 16(1.75,-2.4) 25(1.75,2.4) 26(1.25,2.4) 27(0.75,2.4) 28(0.25,2.4) 29(-0.25,2.4) 30(-0.75,2.4) 31(-1.25,2.4) 32(-1.75,2.4)
  rrect5% 2.1x2.1 smd paste-1000 mask+0: 33(0,0)
  silkscreen extent -3.38,-2.55 2.55,2.55, body extent -2.8,-2.8 2.8,2.8, height 0.25
RNX0012B [mm] "VQFN-HR-12"
  rrect40% 0.6x0.25 smd: 1(-0.9,1.125) 2(-0.9,0.475) 3(-0.9,-0.175) 4(-0.9,-0.675) 8(0.9,-0.675) 9(0.9,-0.175) 10(0.9,0.475) 11(0.9,1.125)
  rrect40% 0.25x0.6 smd: 5(-0.5,-1.4) 6(0,-1.4) 7(0.5,-1.4)
  rrect40% 0.25x1.825 smd paste-0.175: 12(0,0.788)
  body extent -1,-1.5 1,1.5, height 1
Samtec_ERF8-030-01-x-D-EM2 [mm] "Receptacle, 0.8mm, 30x2, Edge Mount"
  rrect20% 0.5x1.48 smd paste-1: 1(-11.6,-2.06) 3(-10.8,-2.06) 5(-10,-2.06) 7(-9.2,-2.06) 9(-8.4,-2.06) 11(-7.6,-2.06) 13(-6.8,-2.06) 15(-6,-2.06) 17(-5.2,-2.06) 19(-4.4,-2.06) 21(-3.6,-2.06) 23(-2.8,-2.06) 25(-2,-2.06) 27(-1.2,-2.06) 29(-0.4,-2.06) 31(0.4,-2.06) 33(1.2,-2.06) 35(2,-2.06) 37(2.8,-2.06) 39(3.6,-2.06) 41(4.4,-2.06) 43(5.2,-2.06) 45(6,-2.06) 47(6.8,-2.06) 49(7.6,-2.06) 51(8.4,-2.06) 53(9.2,-2.06) 55(10,-2.06) 57(10.8,-2.06) 59(11.6,-2.06)
  rrect20% 0.5x1.48 smd far side paste-1: 2(-11.6,-2.06) 4(-10.8,-2.06) 6(-10,-2.06) 8(-9.2,-2.06) 10(-8.4,-2.06) 12(-7.6,-2.06) 14(-6.8,-2.06) 16(-6,-2.06) 18(-5.2,-2.06) 20(-4.4,-2.06) 22(-3.6,-2.06) 24(-2.8,-2.06) 26(-2,-2.06) 28(-1.2,-2.06) 30(-0.4,-2.06) 32(0.4,-2.06) 34(1.2,-2.06) 36(2,-2.06) 38(2.8,-2.06) 40(3.6,-2.06) 42(4.4,-2.06) 44(5.2,-2.06) 46(6,-2.06) 48(6.8,-2.06) 50(7.6,-2.06) 52(8.4,-2.06) 54(9.2,-2.06) 56(10,-2.06) 58(10.8,-2.06) 60(11.6,-2.06)
  rrect7% 1.5x2 smd: MP1(-16.5,-2.2) MP3(16.5,-2.2)
  rrect7% 1.5x2 smd far side: MP2(-16.5,-2.2) MP4(16.5,-2.2)
  silkscreen extent -18.5,-5.2 18,-0.17, body extent -18,-5.2 18,7, height 2.14
Samtec_ERM8-030-01-L-D-EM2 [mm] "Receptacle, 0.8mm, 30x2, Edge mount"
  rect 1.45x0.5 smd: 1(2.075,11.6) 3(2.075,10.8) 5(2.075,10) 7(2.075,9.2) 9(2.075,8.4) 11(2.075,7.6) 13(2.075,6.8) 15(2.075,6) 17(2.075,5.2) 19(2.075,4.4) 21(2.075,3.6) 23(2.075,2.8) 25(2.075,2) 27(2.075,1.2) 29(2.075,0.4) 31(2.075,-0.4) 33(2.075,-1.2) 35(2.075,-2) 37(2.075,-2.8) 39(2.075,-3.6) 41(2.075,-4.4) 43(2.075,-5.2) 45(2.075,-6) 47(2.075,-6.8) 49(2.075,-7.6) 51(2.075,-8.4) 53(2.075,-9.2) 55(2.075,-10) 57(2.075,-10.8) 59(2.075,-11.6)
  rect 1.45x0.5 smd far side: 2(2.075,11.6) 4(2.075,10.8) 6(2.075,10) 8(2.075,9.2) 10(2.075,8.4) 12(2.075,7.6) 14(2.075,6.8) 16(2.075,6) 18(2.075,5.2) 20(2.075,4.4) 22(2.075,3.6) 24(2.075,2.8) 26(2.075,2) 28(2.075,1.2) 30(2.075,0.4) 32(2.075,-0.4) 34(2.075,-1.2) 36(2.075,-2) 38(2.075,-2.8) 40(2.075,-3.6) 42(2.075,-4.4) 44(2.075,-5.2) 46(2.075,-6) 48(2.075,-6.8) 50(2.075,-7.6) 52(2.075,-8.4) 54(2.075,-9.2) 56(2.075,-10) 58(2.075,-10.8) 60(2.075,-11.6)
  rect 2x1 smd: MP1(2.3,15) MP3(2.3,-15)
  rect 2x1 smd far side: MP2(2.3,15) MP4(2.3,-15)
  silkscreen extent 0.2,-16.5 5.2,16.5, body extent -7.75,-16.5 5.2,16.5, height 2.15
Samtec_HTSW-121-07-x-T [mm] "Header, 2.54mm, 21x3, TH"
  rrect50% 1.53x1.53 hole 1.02: 1(-2.54,25.4)
  round 1.53 hole 1.02: 2(0,25.4) 3(2.54,25.4) 4(-2.54,22.86) 5(0,22.86) 6(2.54,22.86) 7(-2.54,20.32) 8(0,20.32) 9(2.54,20.32) 10(-2.54,17.78) 11(0,17.78) 12(2.54,17.78) 13(-2.54,15.24) 14(0,15.24) 15(2.54,15.24) 16(-2.54,12.7) 17(0,12.7) 18(2.54,12.7) 19(-2.54,10.16) 20(0,10.16) 21(2.54,10.16) 22(-2.54,7.62) 23(0,7.62) 24(2.54,7.62) 25(-2.54,5.08) 26(0,5.08) 27(2.54,5.08) 28(-2.54,2.54) 29(0,2.54) 30(2.54,2.54) 31(-2.54,0) 32(0,0) 33(2.54,0) 34(-2.54,-2.54) 35(0,-2.54) 36(2.54,-2.54) 37(-2.54,-5.08) 38(0,-5.08) 39(2.54,-5.08) 40(-2.54,-7.62) 41(0,-7.62) 42(2.54,-7.62) 43(-2.54,-10.16) 44(0,-10.16) 45(2.54,-10.16) 46(-2.54,-12.7) 47(0,-12.7) 48(2.54,-12.7) 49(-2.54,-15.24) 50(0,-15.24) 51(2.54,-15.24) 52(-2.54,-17.78) 53(0,-17.78) 54(2.54,-17.78) 55(-2.54,-20.32) 56(0,-20.32) 57(2.54,-20.32) 58(-2.54,-22.86) 59(0,-22.86) 60(2.54,-22.86) 61(-2.54,-25.4) 62(0,-25.4) 63(2.54,-25.4)
  body extent -3.78,-26.67 3.78,26.67, height 8.38
Schurter_0031-7701-11 [mm] "SMD, 2-Leads, Body 12x5.2mm"
  rrect2% 5x6 smd: 1(-4,0) 2(4,0)
  silkscreen extent -1.1,-2.7 1.1,2.7, body extent -6.04,-2.6 6.04,2.6, height 6
SMA [mm] "Molded Diode, 2-Leads, Body 4.3x2.6mm, IPC Medium Density, based on OnSemi component dimensions and land pattern"
  rect 2x2 smd: 1(-2,0) 2(2,0)
  silkscreen extent -3.66,-1.57 2.79,1.57, body extent -2.6,-1.3 2.6,1.3, height 2.42
SRP5030T [mm] "Bourns"
  rect 2x1.8 smd: 1(-2.25,0) 2(2.25,0)
  silkscreen extent -3.1,-2.8 3.1,2.8, body extent -3,-2.7 3,2.7, height 3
